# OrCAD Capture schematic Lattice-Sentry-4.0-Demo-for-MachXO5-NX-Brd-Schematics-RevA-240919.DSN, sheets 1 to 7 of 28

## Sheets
1 Title Page: title: Sentry 4.0 Board for XO5D; rev: 1.1; note: 305-PD-24-0xxx
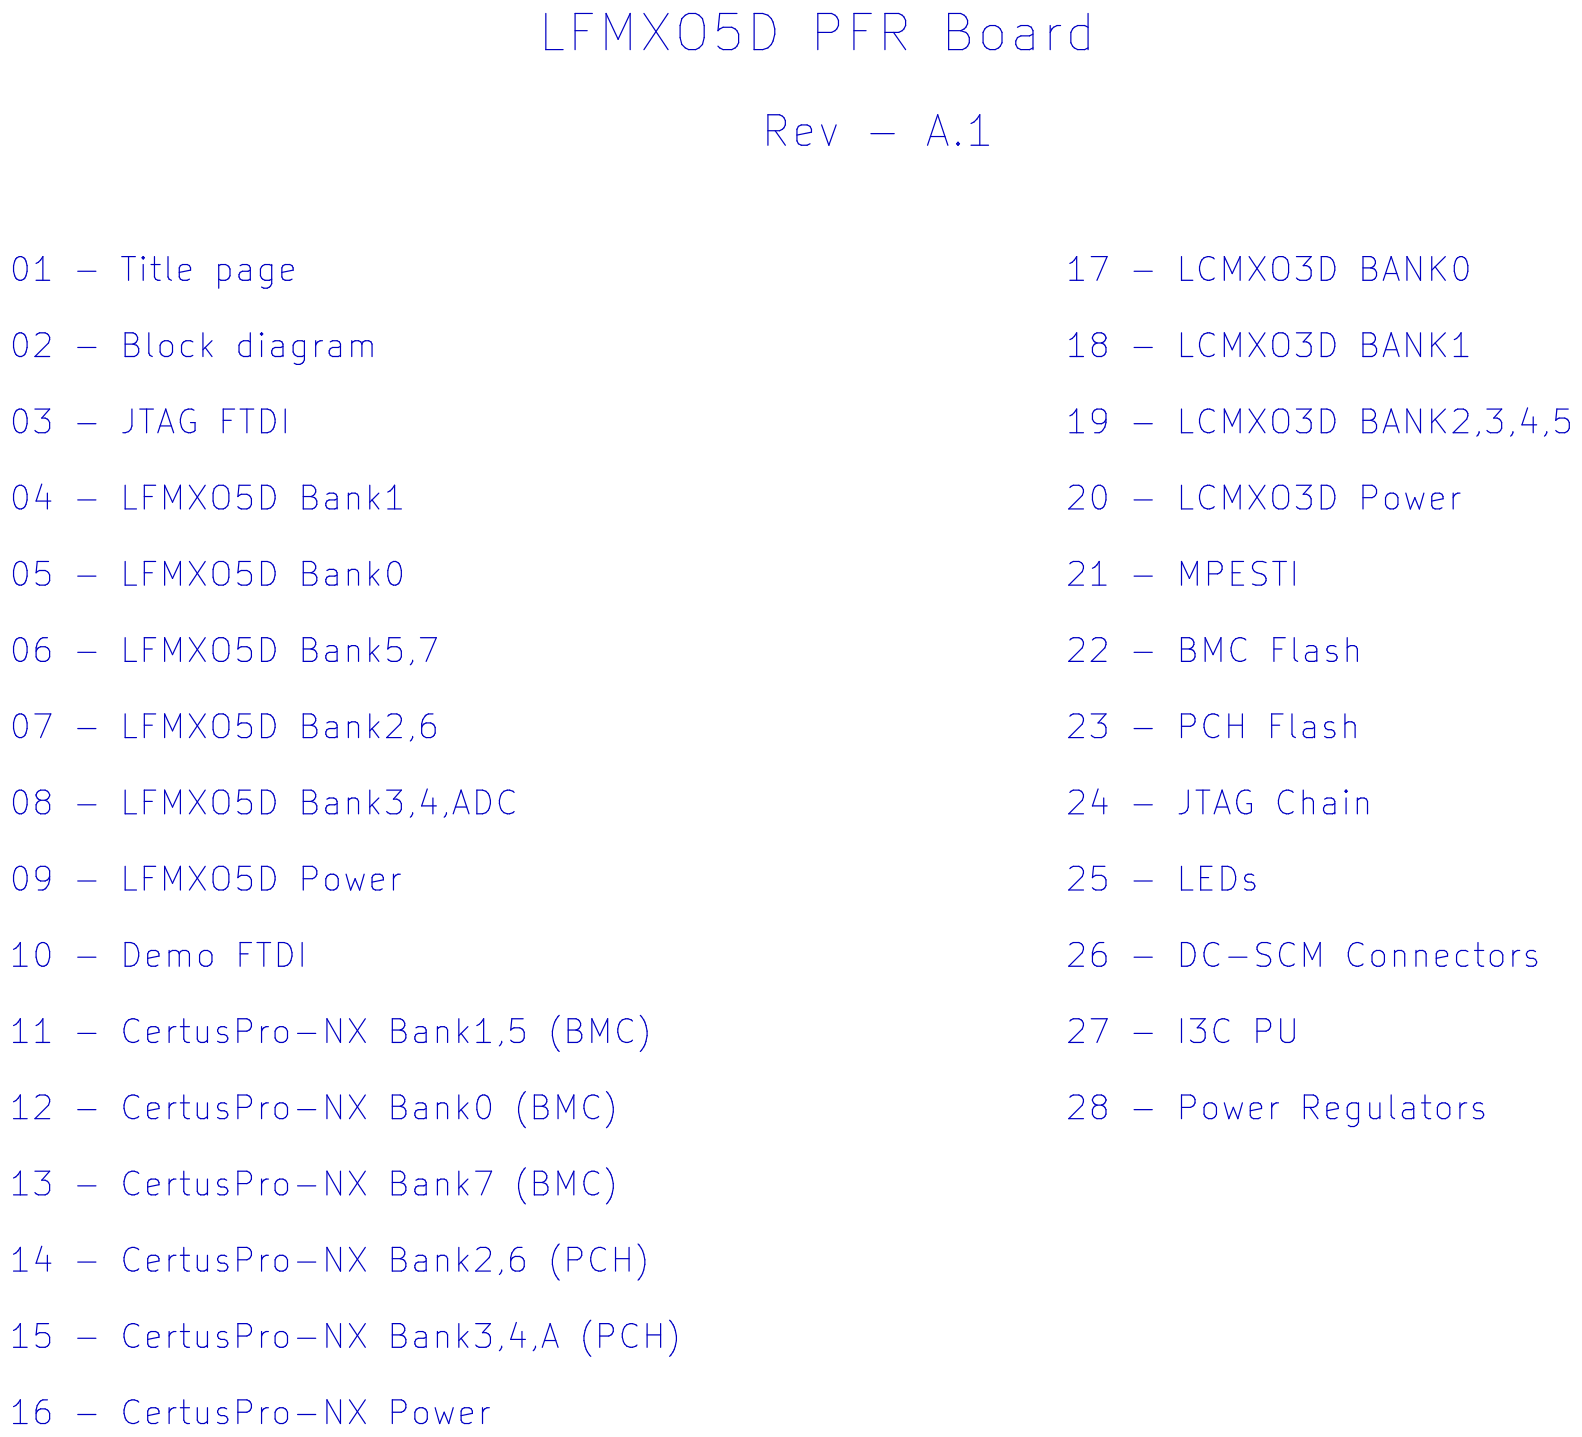
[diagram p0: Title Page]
2 Block Diagram
3 JTAG FTDI: size B
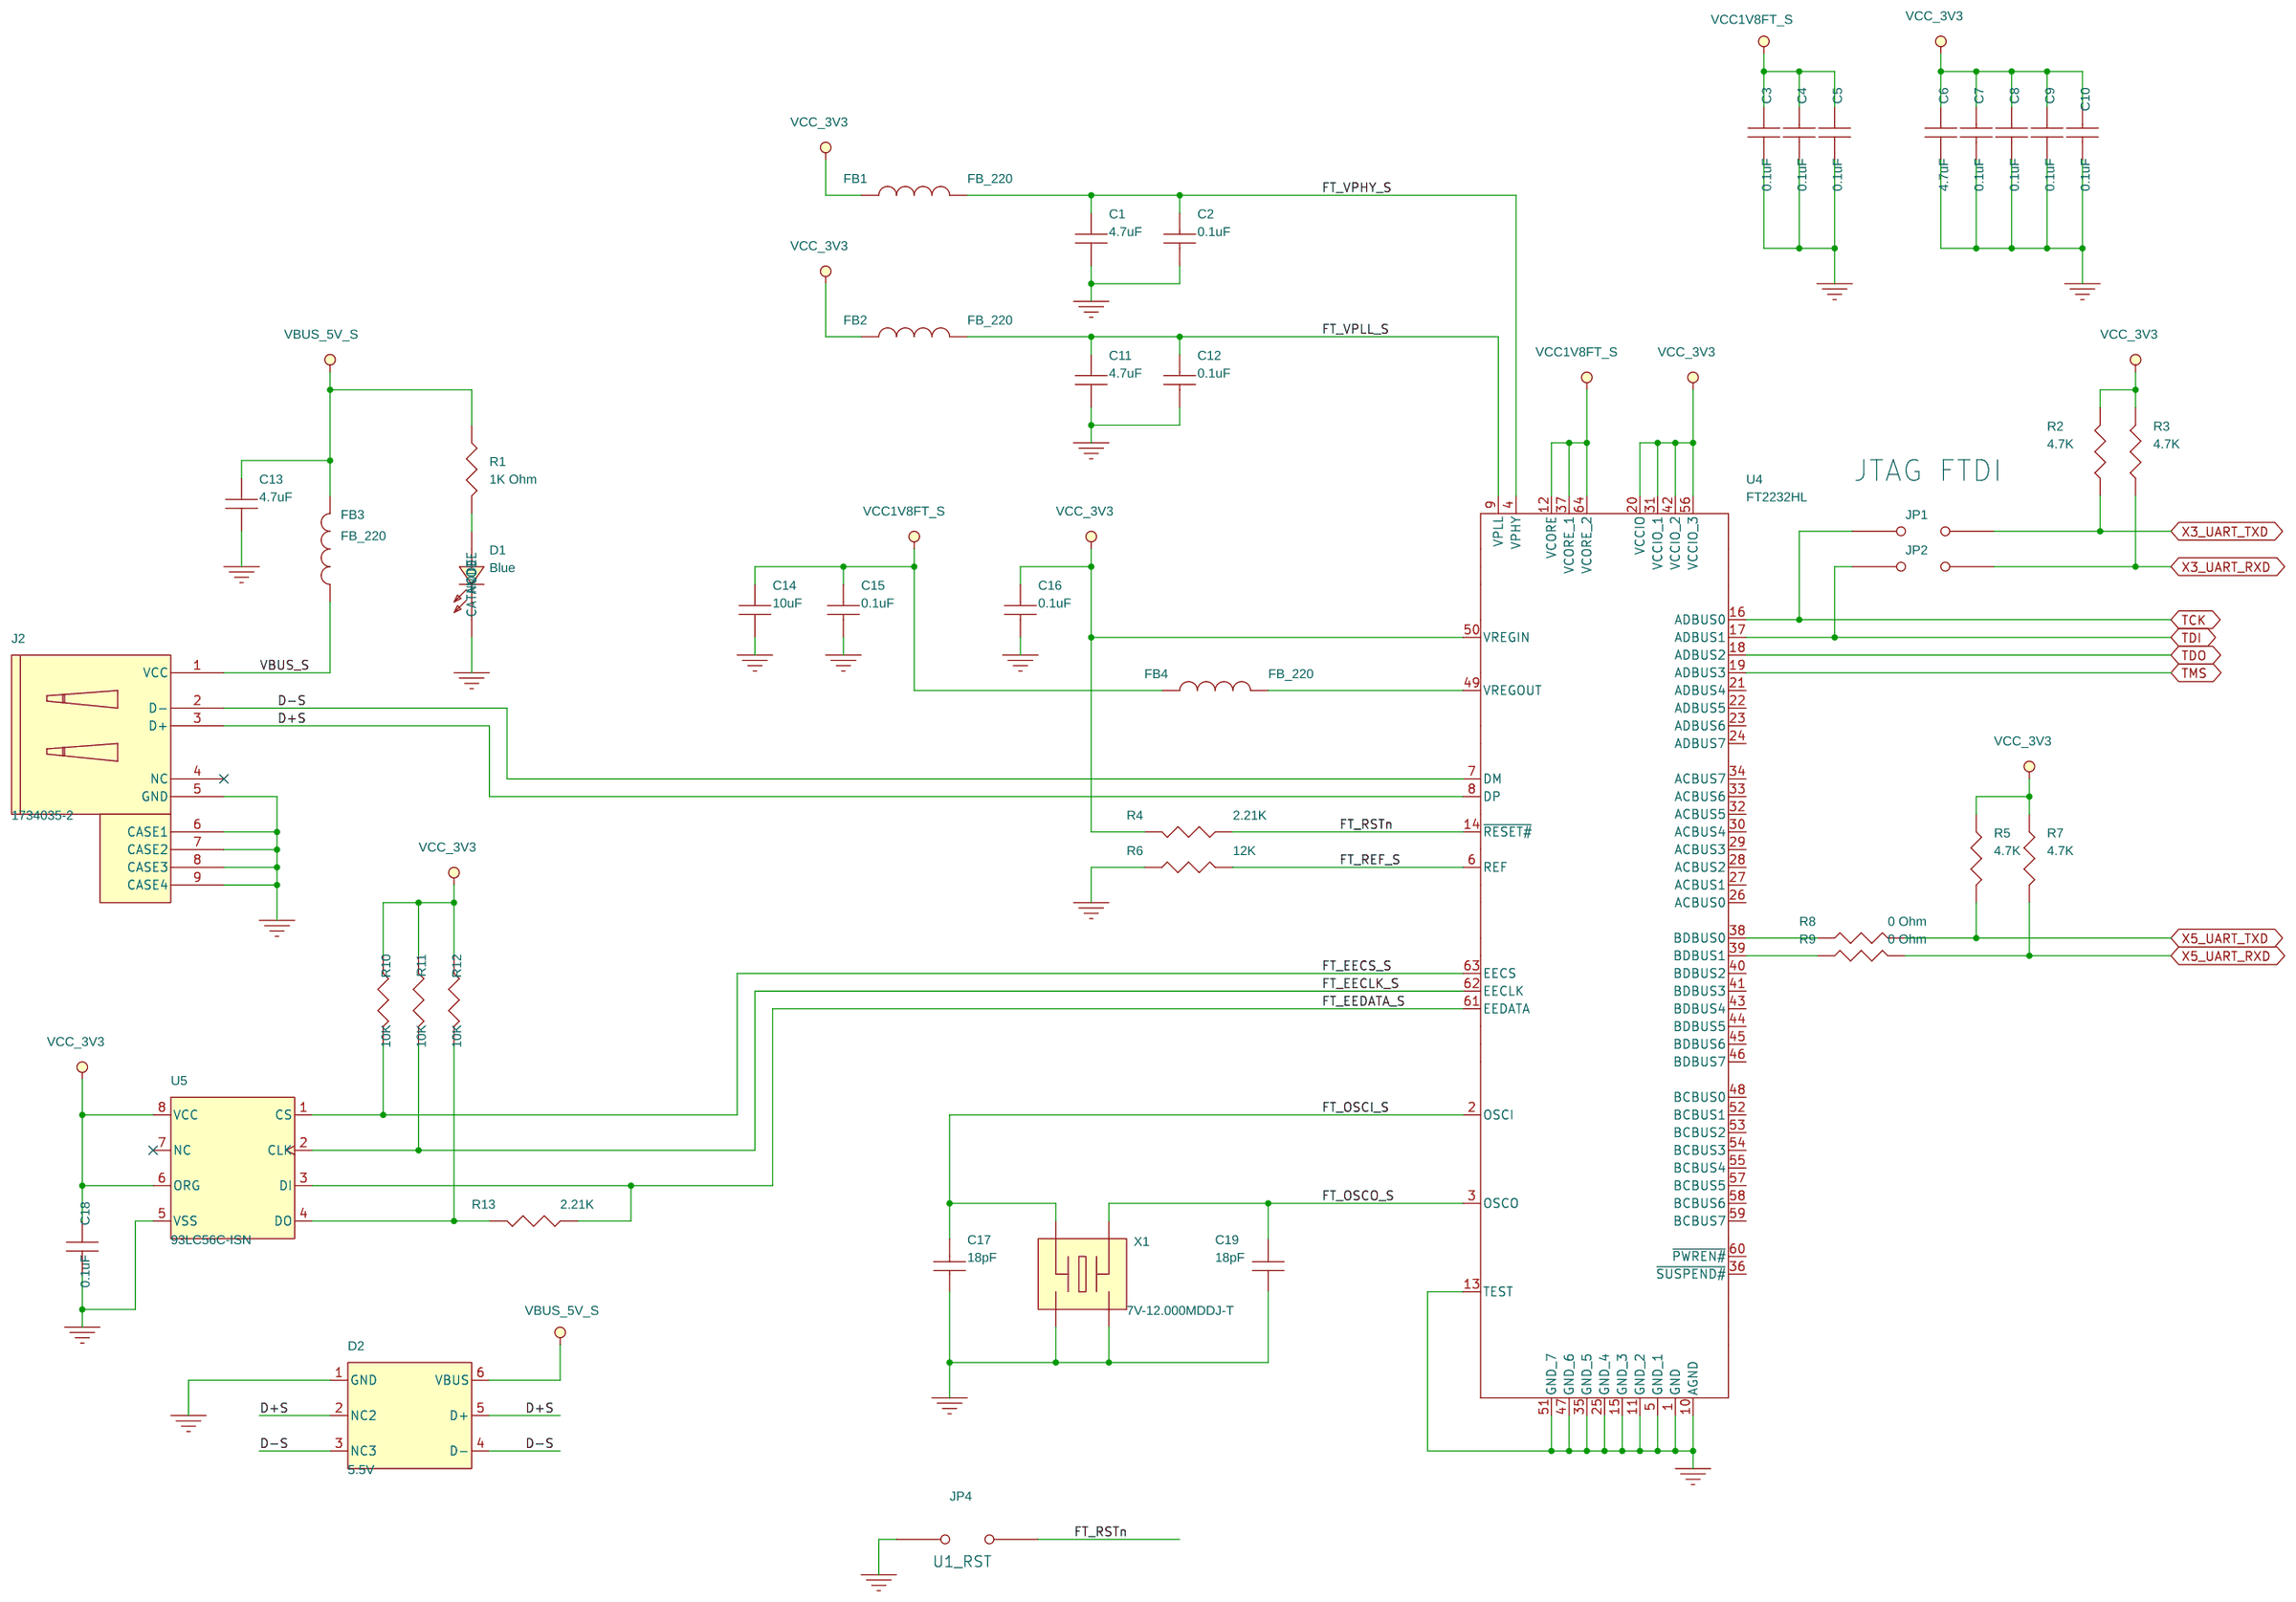
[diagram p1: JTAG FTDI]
4 LFMXO5D Bank1: size B
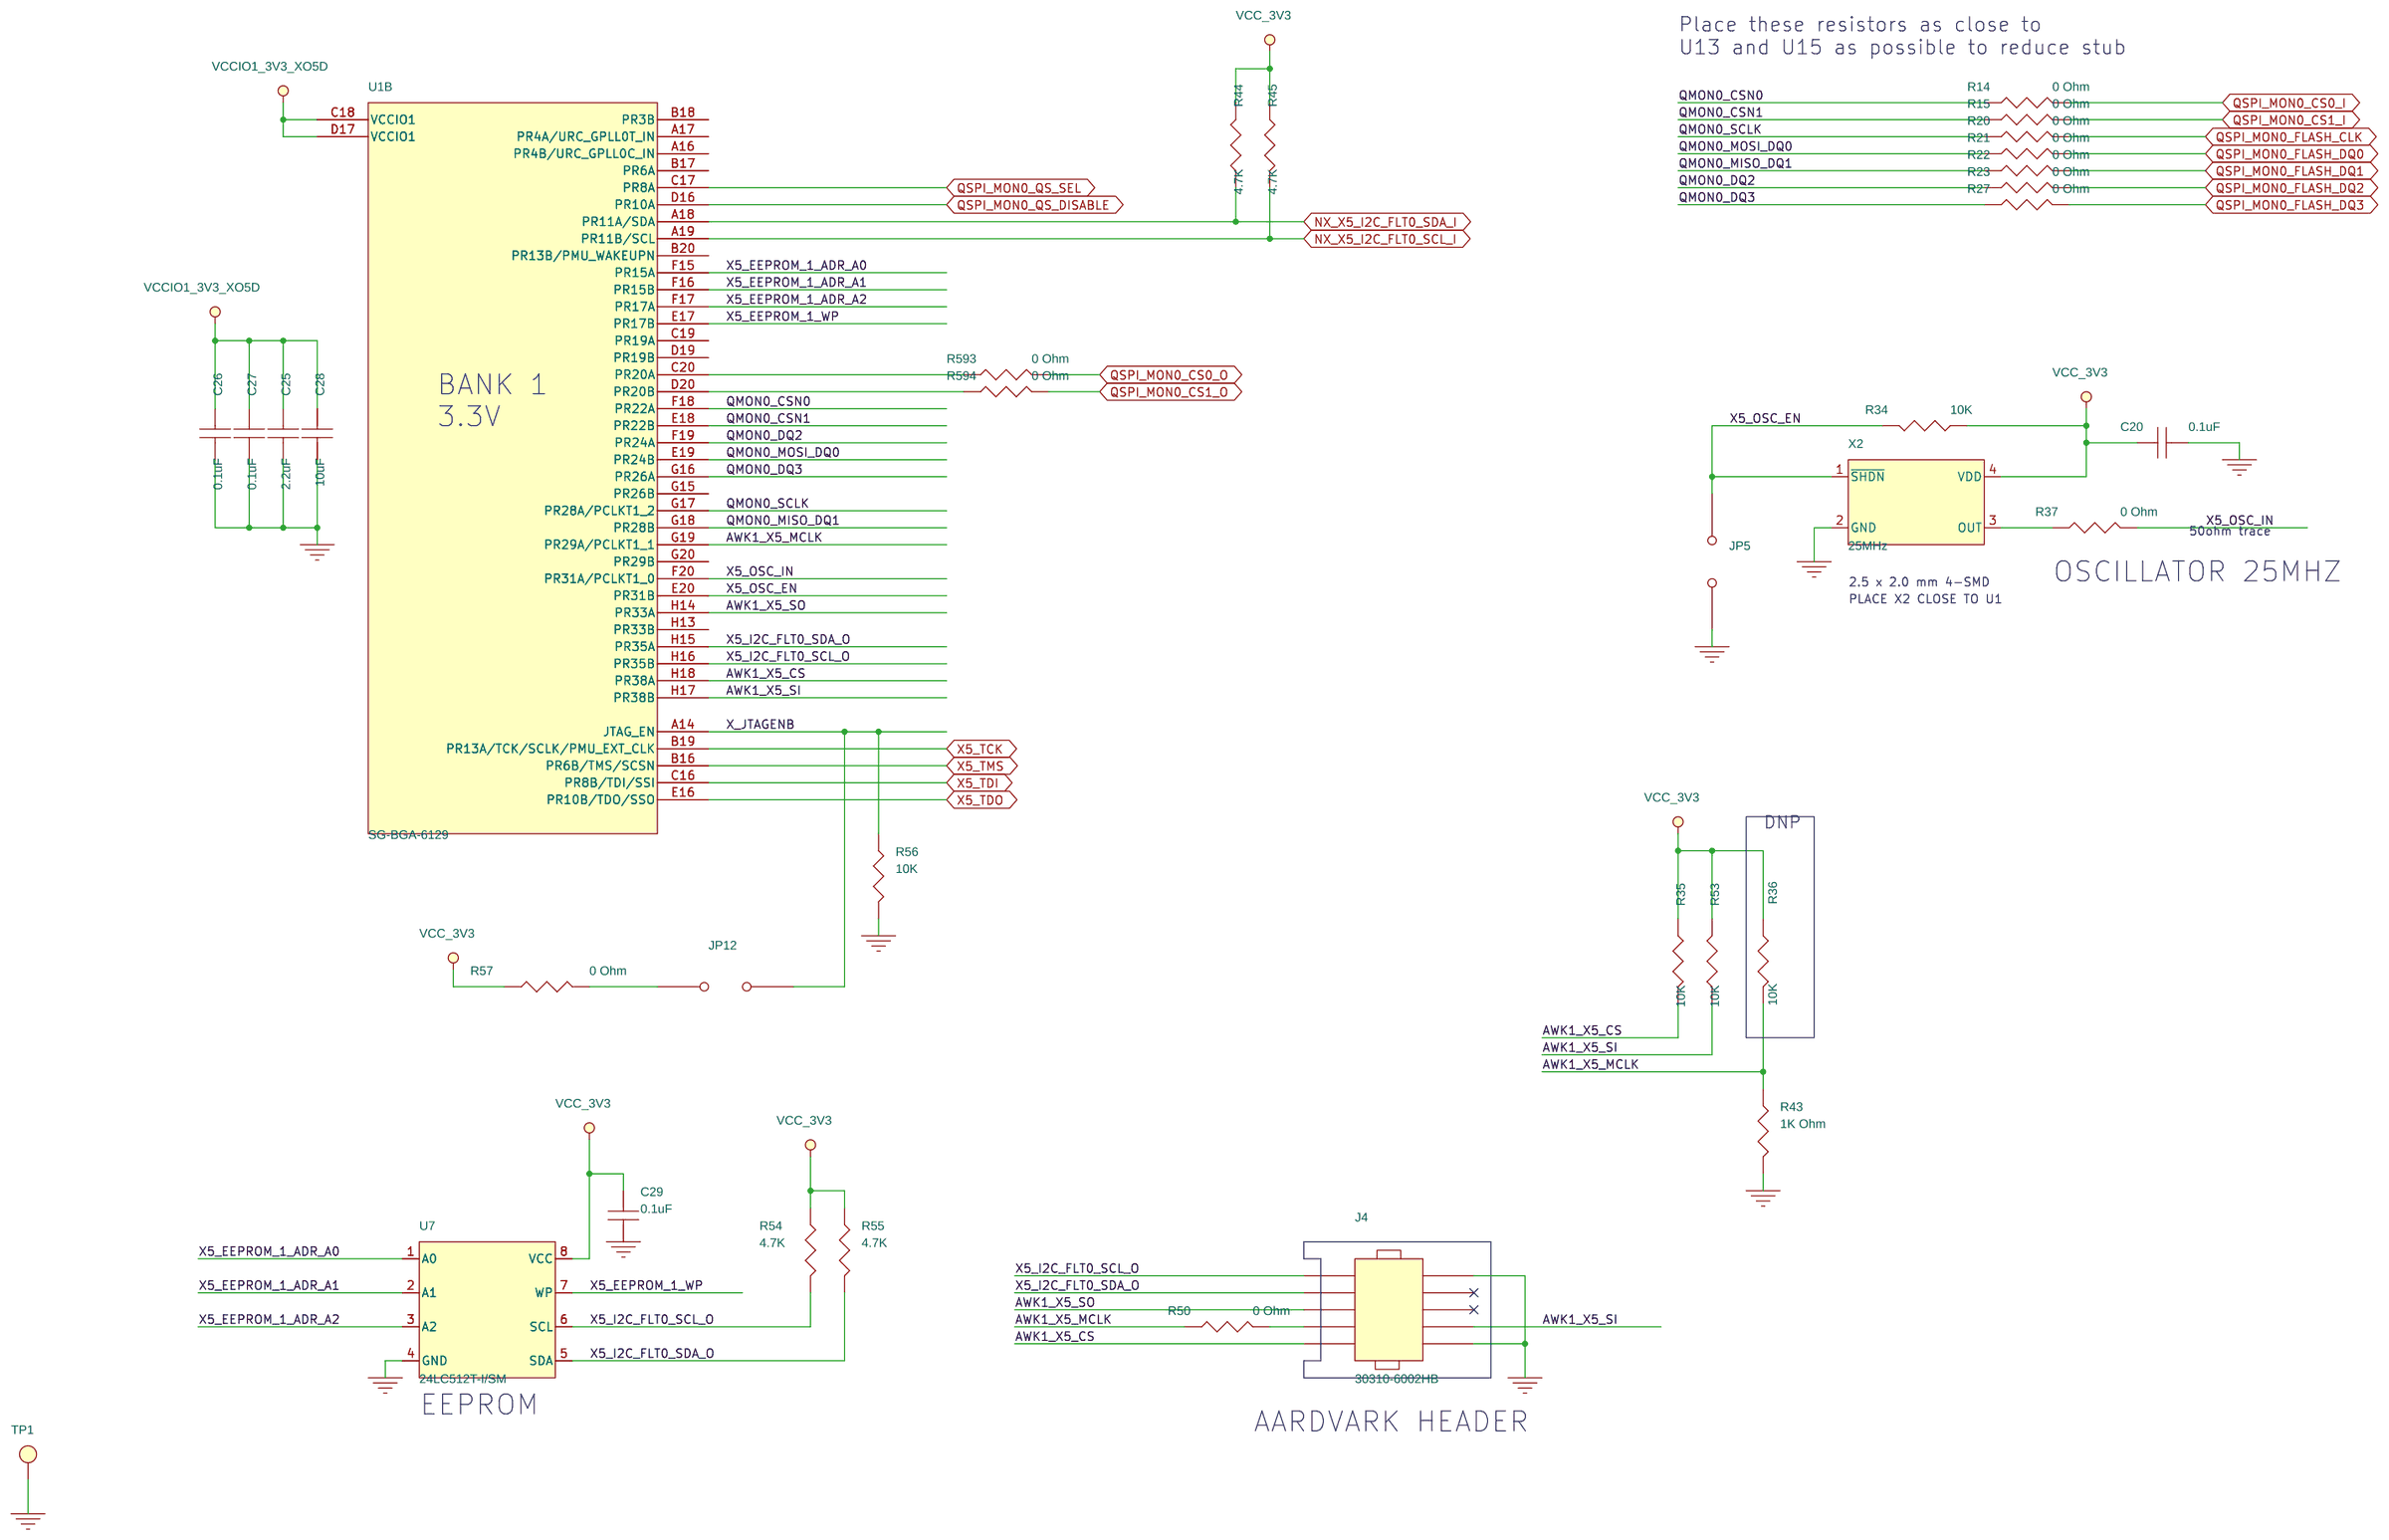
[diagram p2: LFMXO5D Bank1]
5 LFMXO5D Bank0: size B
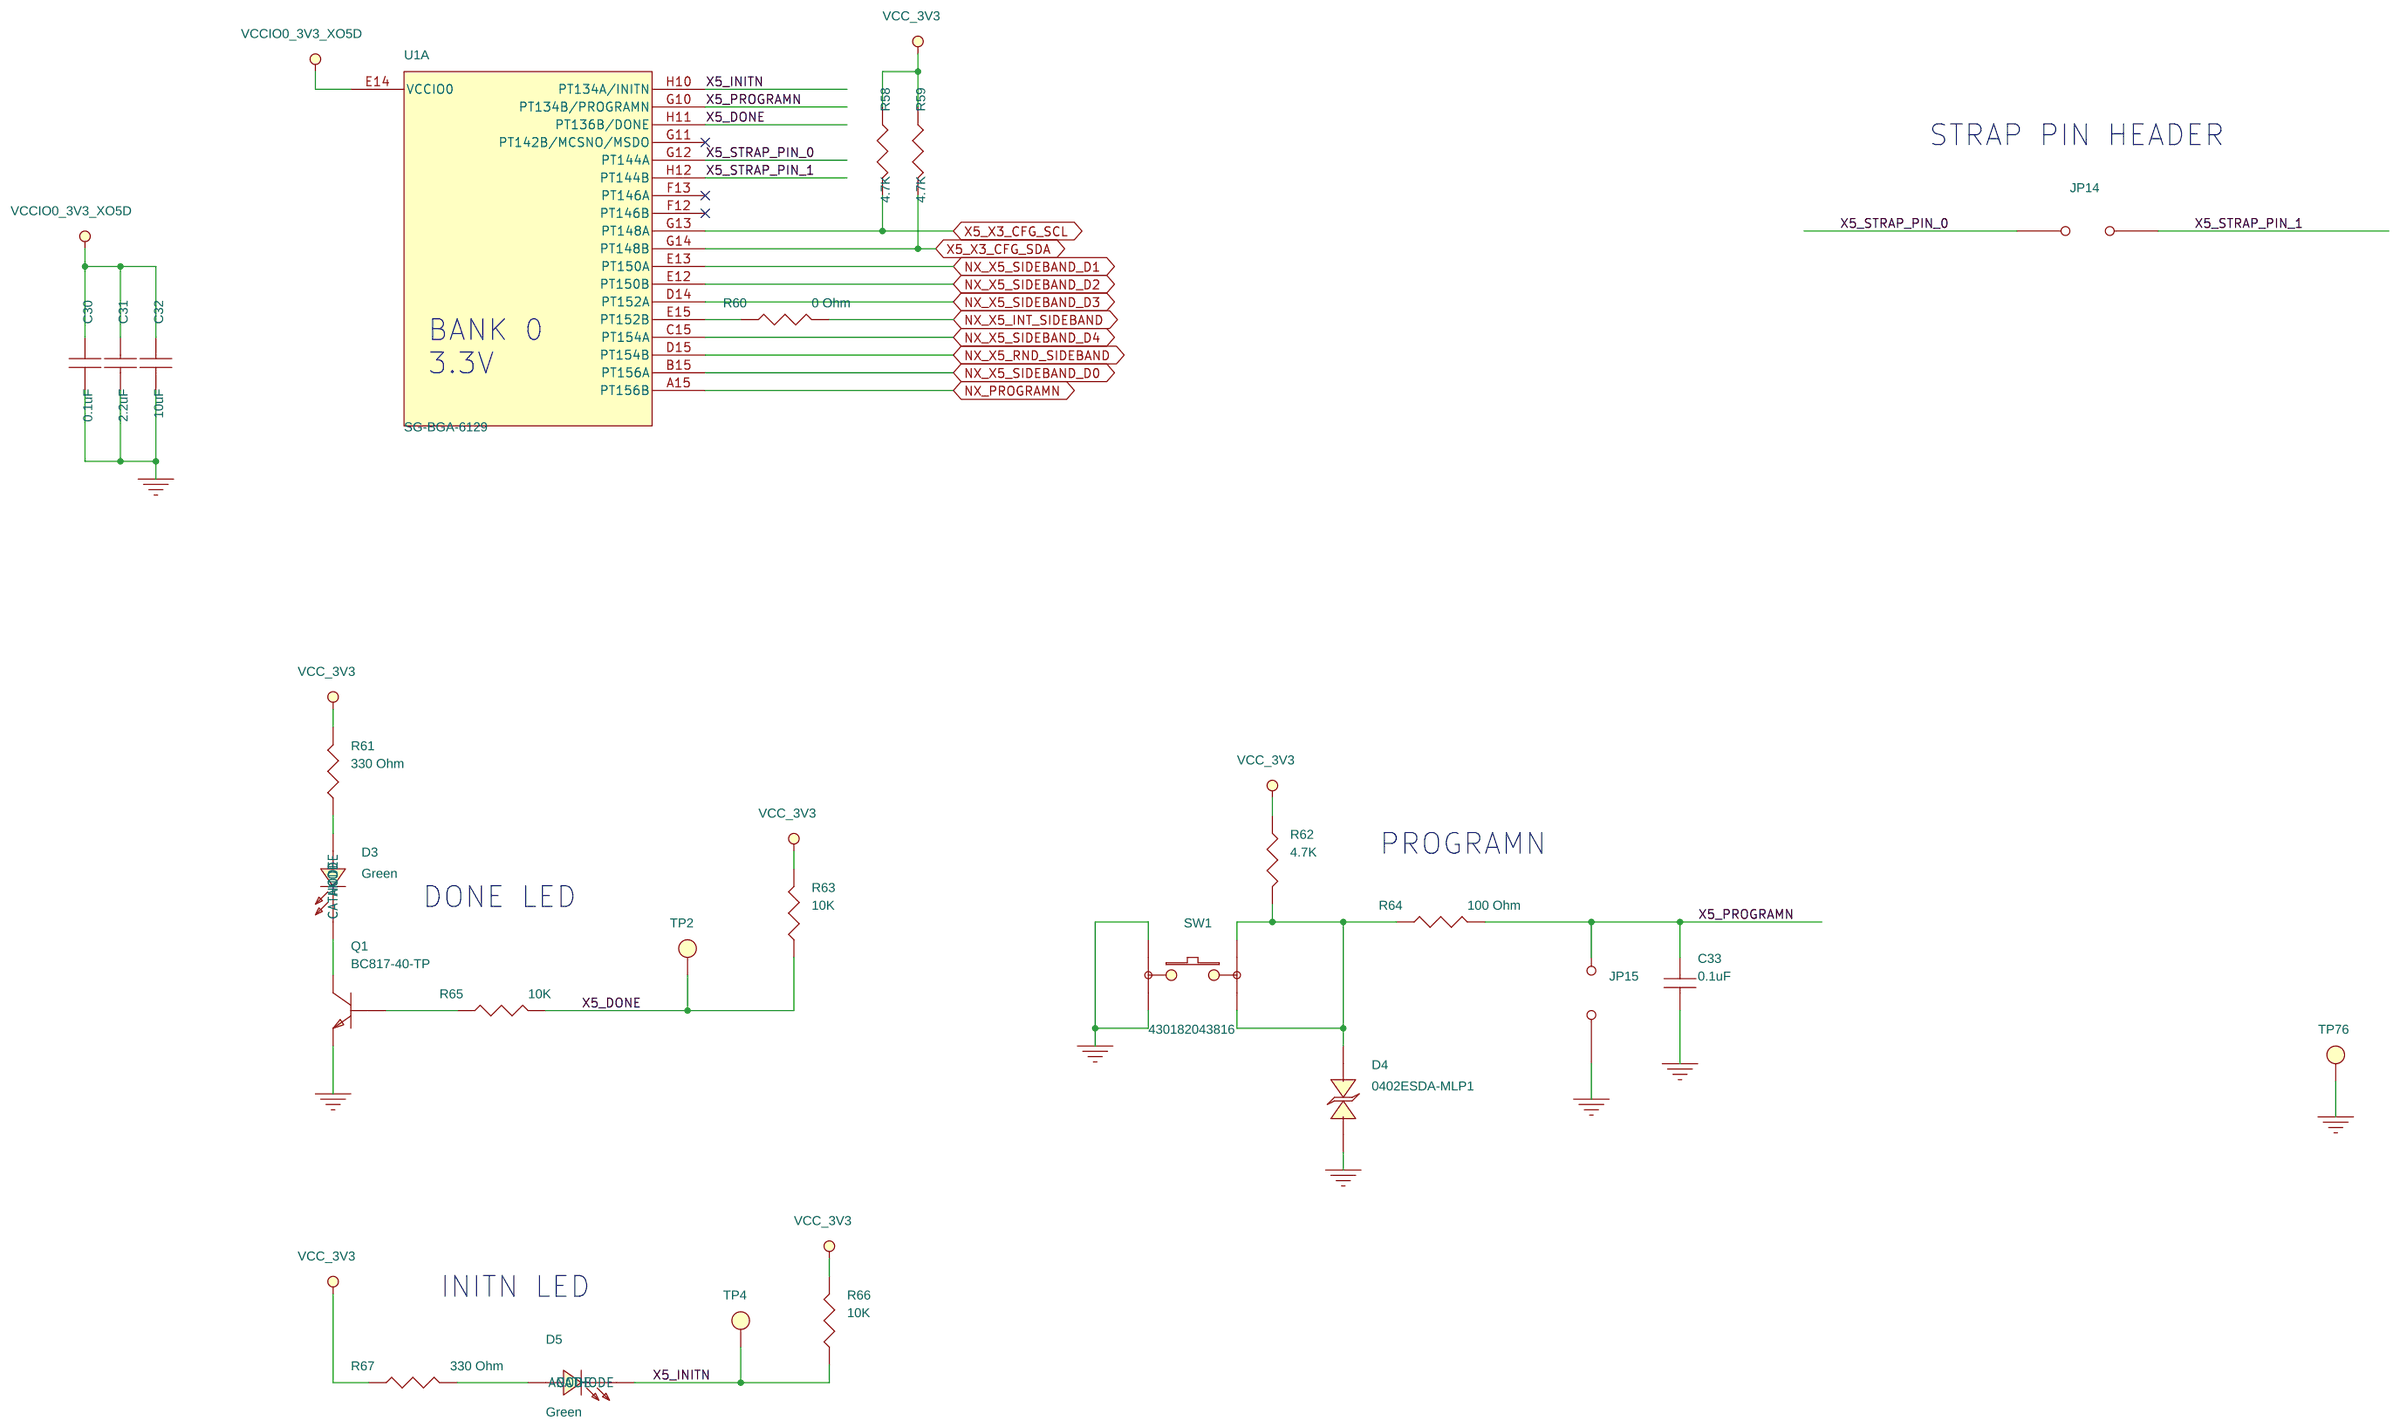
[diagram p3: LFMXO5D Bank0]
6 LFMXO5D Bank5,7: size B
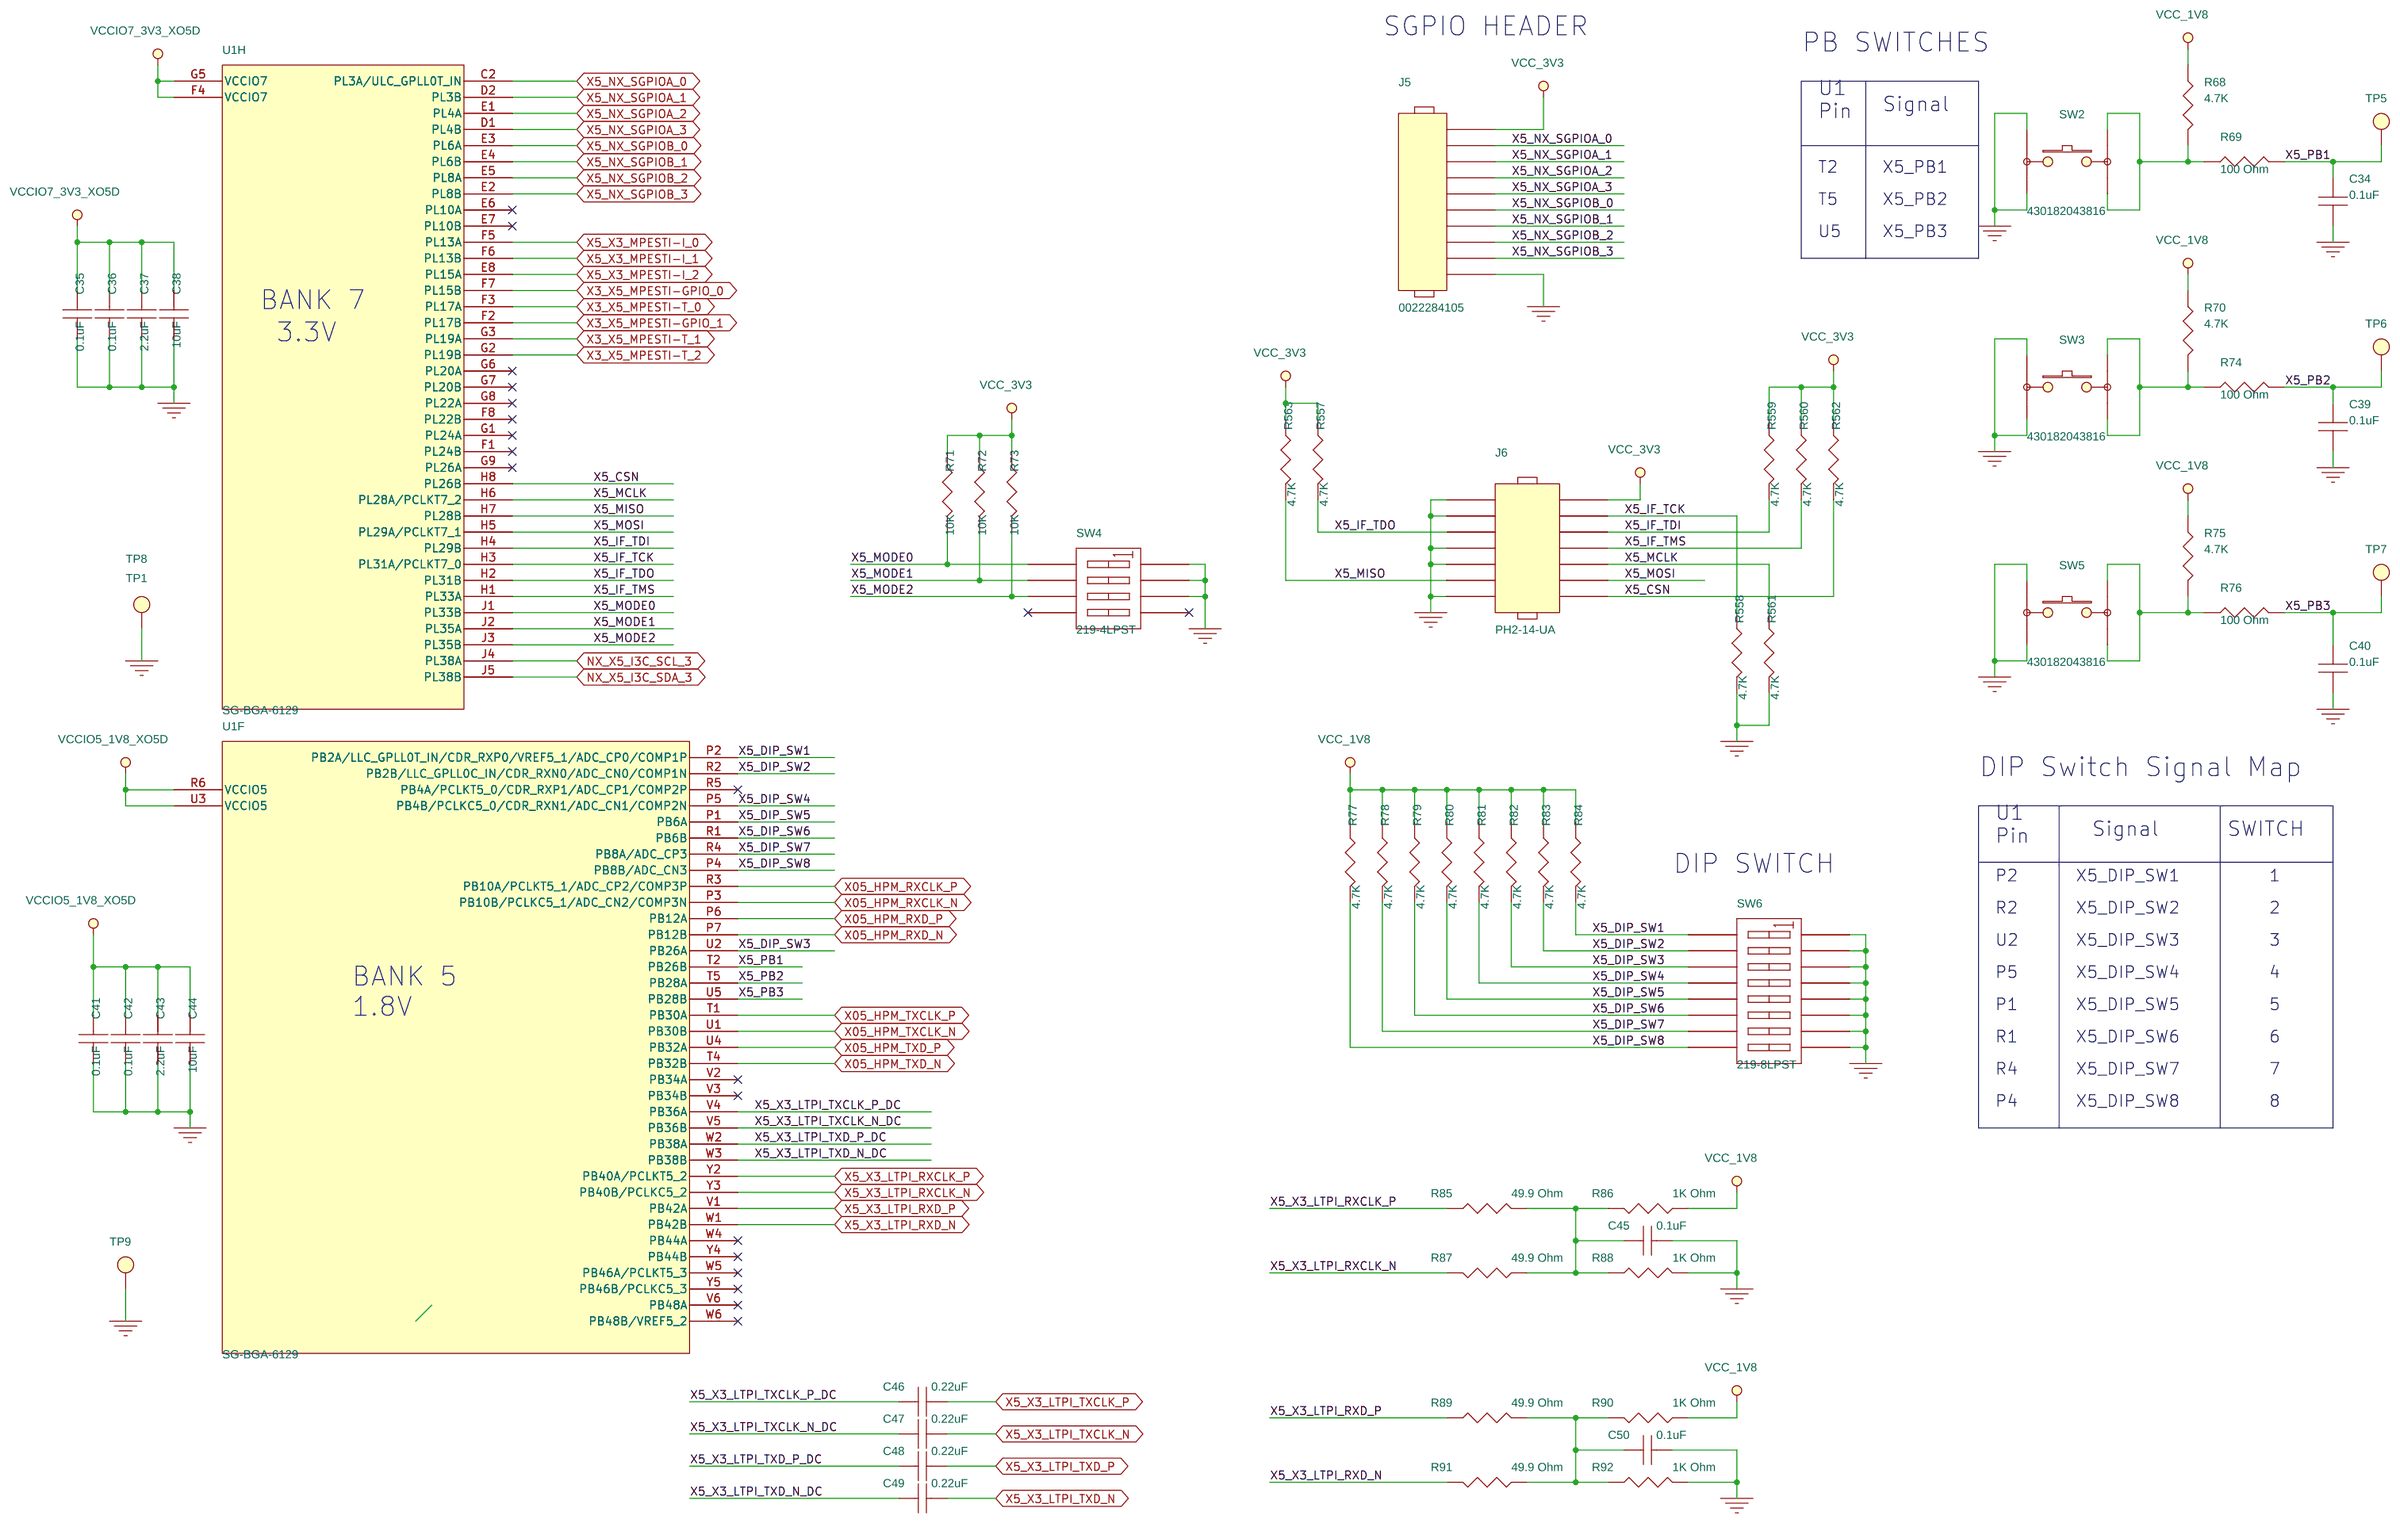
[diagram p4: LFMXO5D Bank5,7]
7 LFMXO5D Bank2,6: size B
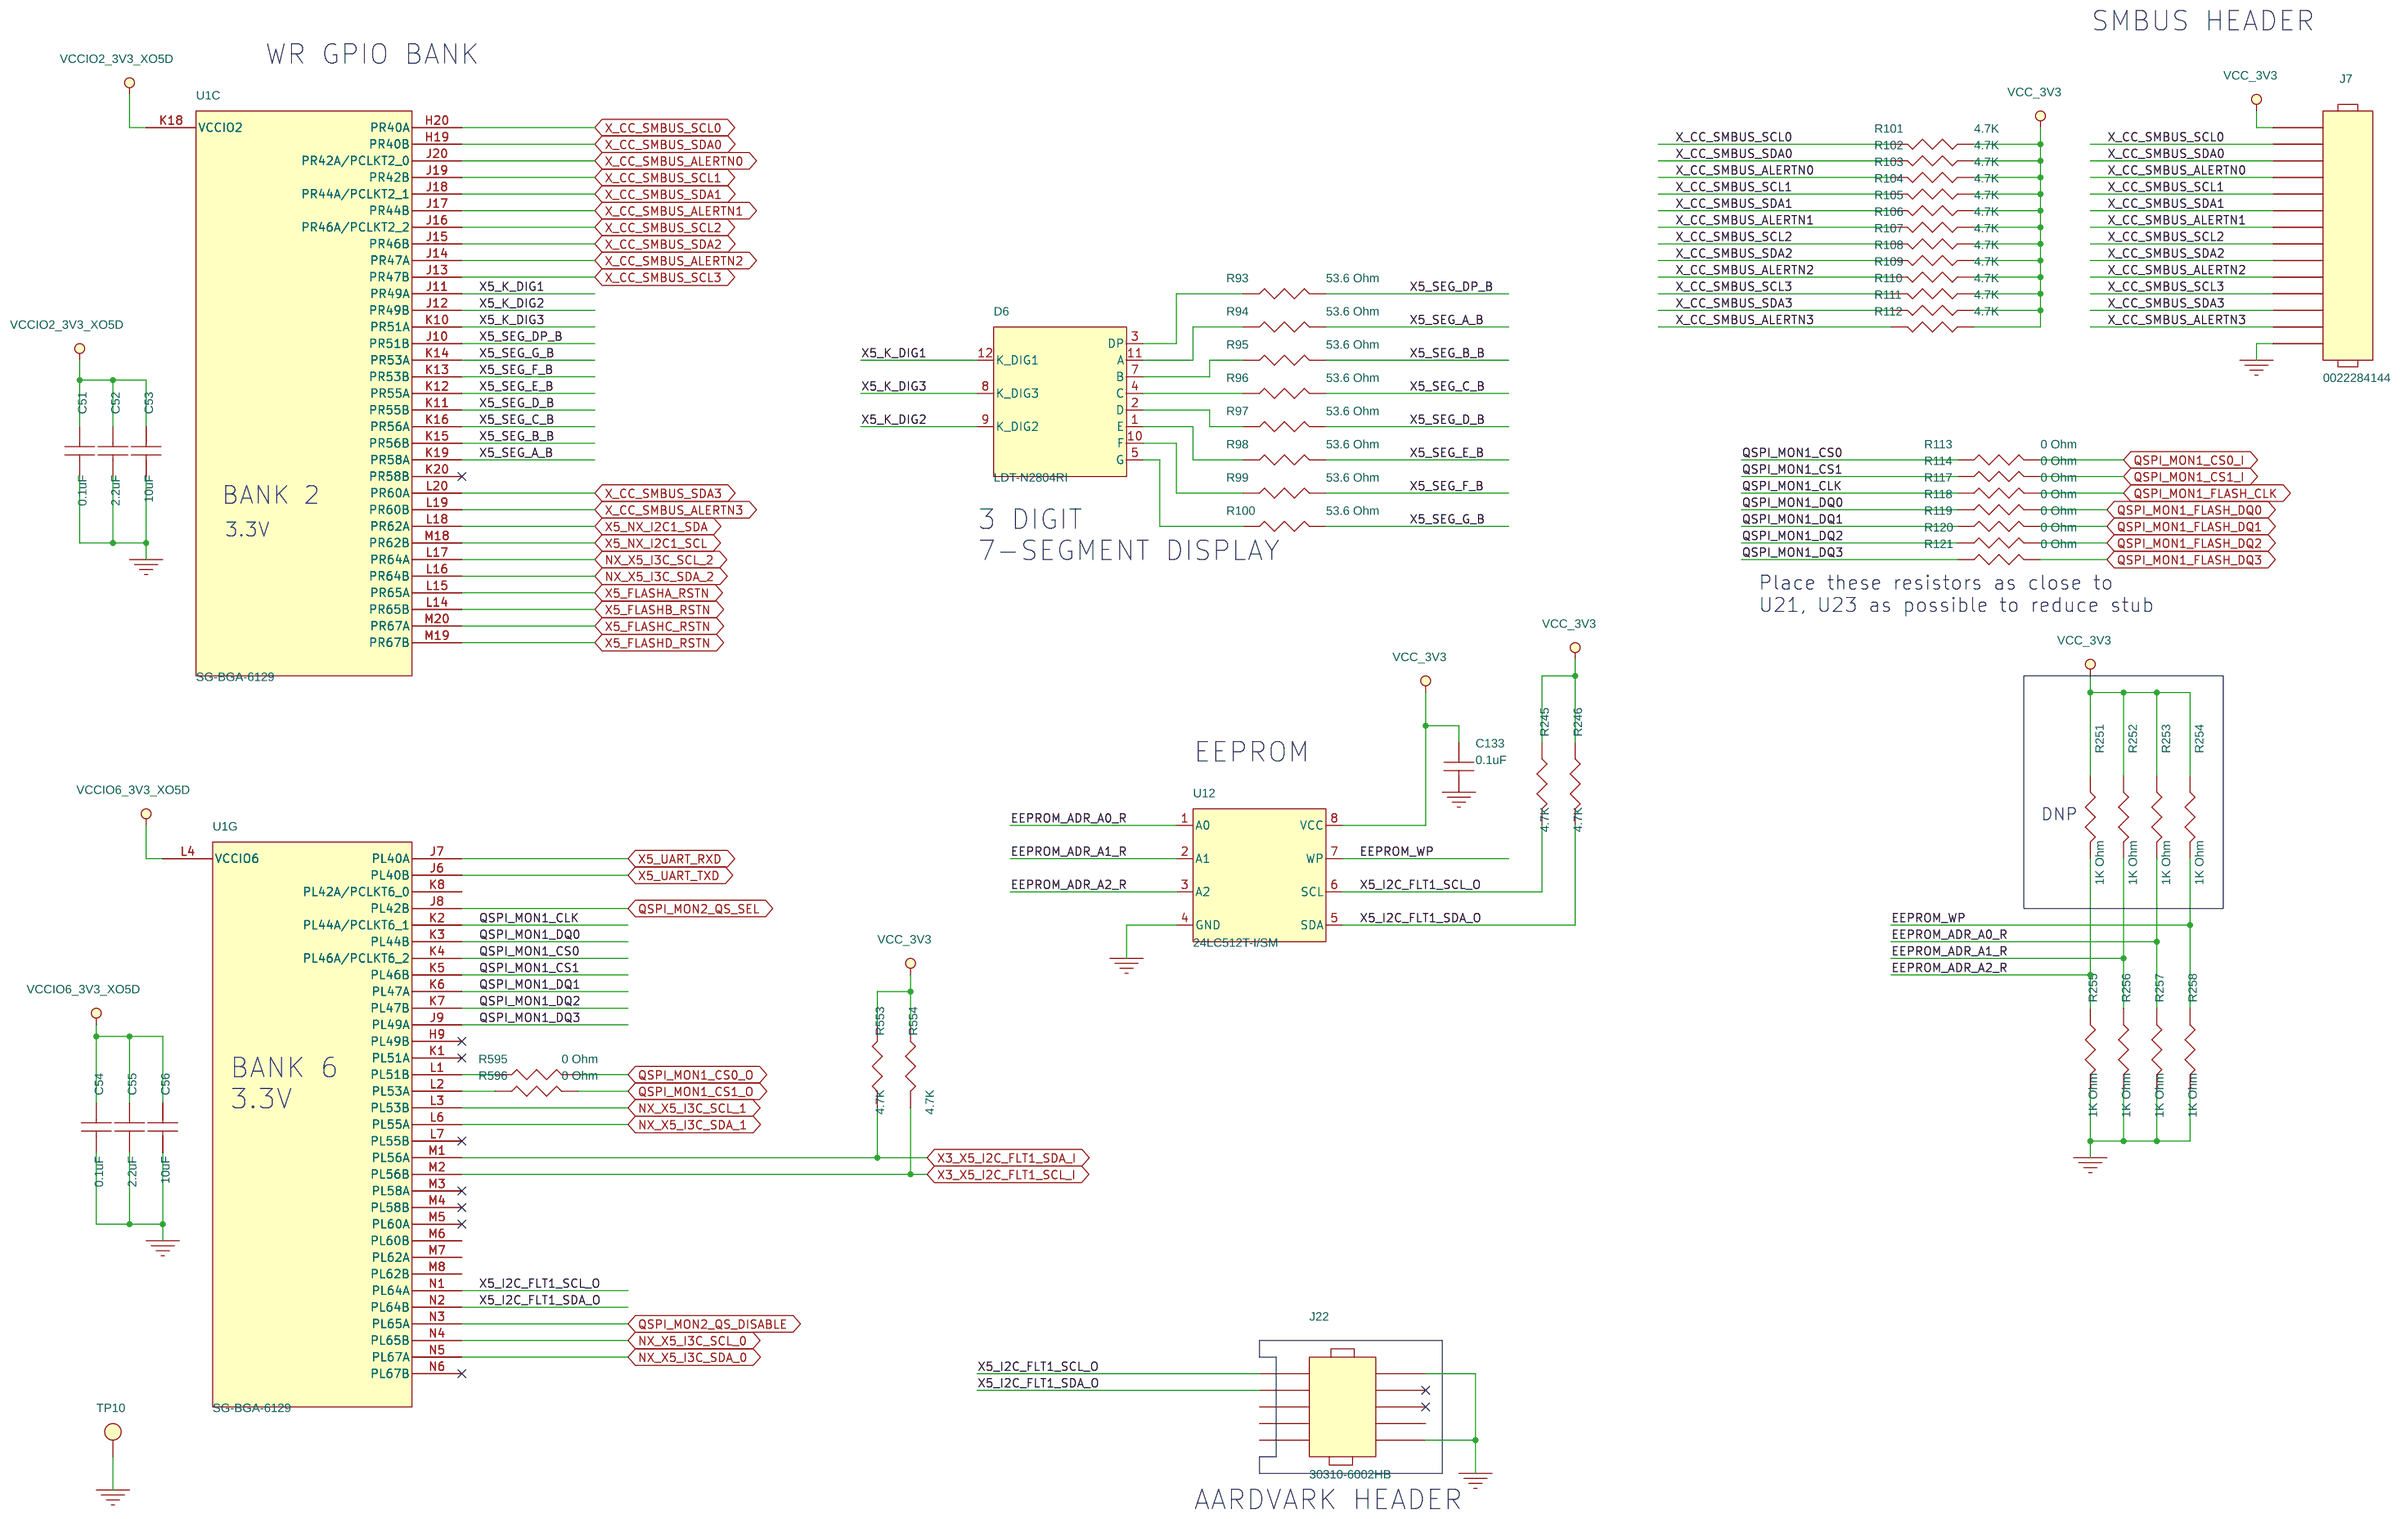
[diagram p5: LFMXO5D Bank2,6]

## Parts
sheet JTAG FTDI
C1  4.7uF  [C0603-L]
C2  0.1uF  [C0402-L]
C3  0.1uF  [C0402-L]
C4  0.1uF  [C0402-L]
C5  0.1uF  [C0402-L]
C6  4.7uF  [C0603-L]
C7  0.1uF  [C0402-L]
C8  0.1uF  [C0402-L]
C9  0.1uF  [C0402-L]
C10  0.1uF  [C0402-L]
C11  4.7uF  [C0603-L]
C12  0.1uF  [C0402-L]
C13  4.7uF  [C0603-L]
C14  10uF  [C0805-L]
C15  0.1uF  [C0402-L]
C16  0.1uF  [C0402-L]
C17  18pF  [C0402-L]
C18  0.1uF  [C0402-L]
C19  18pF  [C0402-L]
D1  Blue  [LED0603]
D2  5.5V  [UDFN6_1P2X1]
FB1  FB_220  [IND_1608_TDK]
FB2  FB_220  [IND_1608_TDK]
FB3  FB_220  [IND_1608_TDK]
FB4  FB_220  [IND_1608_TDK]
J2  1734035-2  [CONN5_USB1734035_TEC]
JP1  Jumper  [CONN2_M20-999_1x2_HRW]
JP2  Jumper  [CONN2_M20-999_1x2_HRW]
JP4  Jumper  [CONN2_M20-999_1x2_HRW]
R1  1K Ohm  [R0402-L]
R2  4.7K  [R0402-L]
R3  4.7K  [R0402-L]
R4  2.21K  [R0402-L]
R5  4.7K  [R0402-L]
R6  12K  [R0402-L]
R7  4.7K  [R0402-L]
R8  0 Ohm  [R0402-L]
R9  0 Ohm  [R0402-L]
R10  10K  [R0402-L]
R11  10K  [R0402-L]
R12  10K  [R0402-L]
R13  2.21K  [R0402-L]
U4  FT2232HL  [64L-LQFP]
U5  93LC56C-ISN  [SOIC8-N]
X1  7V-12.000MDDJ-T  [SMD_0MAHE-T_TXC-L]
sheet LFMXO5D Bank0
C30  0.1uF  [C0402-L]
C31  2.2uF  [C0603-L]
C32  10uF  [C0805-L]
C33  0.1uF  [C0402-L]
D3  Green  [LED0603]
D4  0402ESDA-MLP1  [TVS0402]
D5  Green  [LED0603]
JP14  Jumper  [CONN2_M20-999_1x2_HRW]
JP15  Jumper  [CONN2_M20-999_1x2_HRW]
Q1  BC817-40-TP  [SOT-23-3]
R58  4.7K  [R0402-L]
R59  4.7K  [R0402-L]
R60  0 Ohm  [R0402-L]
R61  330 Ohm  [R0402-L]
R62  4.7K  [R0402-L]
R63  10K  [R0402-L]
R64  100 Ohm  [R0402-L]
R65  10K  [R0402-L]
R66  10K  [R0402-L]
R67  330 Ohm  [R0402-L]
SW1  430182043816  [SOIC_82043816_WRE]
TP2  TP1  [TPd39c60]
TP4  TP1  [TPd39c60]
TP76  TP1  [TPd39c60]
sheet LFMXO5D Bank1
C20  0.1uF  [C0402-L]
C25  2.2uF  [C0603-L]
C26  0.1uF  [C0402-L]
C27  0.1uF  [C0402-L]
C28  10uF  [C0805-L]
C29  0.1uF  [C0402-L]
J4  30310-6002HB  [CONN_30310-6002HB_3MM]
JP5  Jumper  [CONN2_M20-999_1x2_HRW]
JP12  Jumper  [CONN2_M20-999_1x2_HRW]
R14  0 Ohm  [R0402-L]
R15  0 Ohm  [R0402-L]
R20  0 Ohm  [R0402-L]
R21  0 Ohm  [R0402-L]
R22  0 Ohm  [R0402-L]
R23  0 Ohm  [R0402-L]
R27  0 Ohm  [R0402-L]
R34  10K  [R0402-L]
R35  10K  [R0402-L]
R36  10K  [R0402-L]
R37  0 Ohm  [R0402-L]
R43  1K Ohm  [R0402-L]
R44  4.7K  [R0402-L]
R45  4.7K  [R0402-L]
R50  0 Ohm  [R0402-L]
R53  10K  [R0402-L]
R54  4.7K  [R0402-L]
R55  4.7K  [R0402-L]
R56  10K  [R0402-L]
R57  0 Ohm  [R0402-L]
R593  0 Ohm  [R0402-L]
R594  0 Ohm  [R0402-L]
TP1  TP1  [TPd39c60]
U7  24LC512T-I/SM  [SOIC8-W_MC_MCH]
X2  25MHz  [ECS-2520MV_ECS]
sheet LFMXO5D Bank2,6
C51  0.1uF  [C0402-L]
C52  2.2uF  [C0603-L]
C53  10uF  [C0805-L]
C54  0.1uF  [C0402-L]
C55  2.2uF  [C0603-L]
C56  10uF  [C0805-L]
C133  0.1uF  [C0402-L]
D6  LDT-N2804RI  [LDT-N2804RI_LUM]
J7  0022284144  [22-28-4144_MOL]
J22  30310-6002HB  [CONN_30310-6002HB_3MM]
R93  53.6 Ohm  [R0402-L]
R94  53.6 Ohm  [R0402-L]
R95  53.6 Ohm  [R0402-L]
R96  53.6 Ohm  [R0402-L]
R97  53.6 Ohm  [R0402-L]
R98  53.6 Ohm  [R0402-L]
R99  53.6 Ohm  [R0402-L]
R100  53.6 Ohm  [R0402-L]
R101  4.7K  [R0402-L]
R102  4.7K  [R0402-L]
R103  4.7K  [R0402-L]
R104  4.7K  [R0402-L]
R105  4.7K  [R0402-L]
R106  4.7K  [R0402-L]
R107  4.7K  [R0402-L]
R108  4.7K  [R0402-L]
R109  4.7K  [R0402-L]
R110  4.7K  [R0402-L]
R111  4.7K  [R0402-L]
R112  4.7K  [R0402-L]
R113  0 Ohm  [R0402-L]
R114  0 Ohm  [R0402-L]
R117  0 Ohm  [R0402-L]
R118  0 Ohm  [R0402-L]
R119  0 Ohm  [R0402-L]
R120  0 Ohm  [R0402-L]
R121  0 Ohm  [R0402-L]
R245  4.7K  [R0402-L]
R246  4.7K  [R0402-L]
R251  1K Ohm  [R0402-L]
R252  1K Ohm  [R0402-L]
R253  1K Ohm  [R0402-L]
R254  1K Ohm  [R0402-L]
R255  1K Ohm  [R0402-L]
R256  1K Ohm  [R0402-L]
R257  1K Ohm  [R0402-L]
R258  1K Ohm  [R0402-L]
R553  4.7K  [R0402-L]
R554  4.7K  [R0402-L]
R595  0 Ohm  [R0402-L]
R596  0 Ohm  [R0402-L]
TP10  TP1  [TPd39c60]
U12  24LC512T-I/SM  [SOIC8-W_MC_MCH]
sheet LFMXO5D Bank5,7
C34  0.1uF  [C0402-L]
C35  0.1uF  [C0402-L]
C36  0.1uF  [C0402-L]
C37  2.2uF  [C0603-L]
C38  10uF  [C0805-L]
C39  0.1uF  [C0402-L]
C40  0.1uF  [C0402-L]
C41  0.1uF  [C0402-L]
C42  0.1uF  [C0402-L]
C43  2.2uF  [C0603-L]
C44  10uF  [C0805-L]
C45  0.1uF  [C0402-L]
C46  0.22uF  [C0402-L]
C47  0.22uF  [C0402-L]
C48  0.22uF  [C0402-L]
C49  0.22uF  [C0402-L]
C50  0.1uF  [C0402-L]
J5  0022284105  [22-28-4105_MOL]
J6  PH2-14-UA  [CONN_PH2-14-UA_AT]
R68  4.7K  [R0402-L]
R69  100 Ohm  [R0402-L]
R70  4.7K  [R0402-L]
R71  10K  [R0402-L]
R72  10K  [R0402-L]
R73  10K  [R0402-L]
R74  100 Ohm  [R0402-L]
R75  4.7K  [R0402-L]
R76  100 Ohm  [R0402-L]
R77  4.7K  [R0402-L]
R78  4.7K  [R0402-L]
R79  4.7K  [R0402-L]
R80  4.7K  [R0402-L]
R81  4.7K  [R0402-L]
R82  4.7K  [R0402-L]
R83  4.7K  [R0402-L]
R84  4.7K  [R0402-L]
R85  49.9 Ohm  [R0402-L]
R86  1K Ohm  [R0402-L]
R87  49.9 Ohm  [R0402-L]
R88  1K Ohm  [R0402-L]
R89  49.9 Ohm  [R0402-L]
R90  1K Ohm  [R0402-L]
R91  49.9 Ohm  [R0402-L]
R92  1K Ohm  [R0402-L]
R557  4.7K  [R0402-L]
R558  4.7K  [R0402-L]
R559  4.7K  [R0402-L]
R560  4.7K  [R0402-L]
R561  4.7K  [R0402-L]
R562  4.7K  [R0402-L]
R563  4.7K  [R0402-L]
SW2  430182043816  [SOIC_82043816_WRE]
SW3  430182043816  [SOIC_82043816_WRE]
SW4  219-4LPST  [219-4LP_CTS]
SW5  430182043816  [SOIC_82043816_WRE]
SW6  219-8LPST  [219-8LPST_CTS]
TP5  TP1  [TPd39c60]
TP6  TP1  [TPd39c60]
TP7  TP1  [TPd39c60]
TP8  TP1  [TPd39c60]
TP9  TP1  [TPd39c60]
U1  SG-BGA-6129  [bga400_socket]  (sections A,B,C,D,E,F,G,H,I,J,K,L)

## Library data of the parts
C1 C6 C11 C13 = CAP_NP: 4.7 µF ±10% 25V Ceramic Capacitor X5R 0603 (1608 Metric); Manufacturer: TDK; Manufacturer Part Number: C1608X5R1E475K080AC; Part Number: C1608X5R1E475K080AC; Part type: Ceramic; Tolerance: 10%; Voltage: 25V; Datasheet: https://product.tdk.com/system/files/dam/doc/product/capacitor/ceramic/mlcc/catalog/mlcc_commercial_general_en.pdf
C2-C5 C7-C10 C12 C15 C16 C18 C20 C26 C27 C29 C30 C33-C36 C39-C42 C45 C50 C51 C54 C133 = CAP_NP: 0.1 µF ±10% 50V Ceramic Capacitor X7R 0402 (1005 Metric); Manufacturer: Murata; Manufacturer Part Number: GRM155R71H104KE14J; Part Number: GRM155R71H104KE14J; Part type: Ceramic; Tolerance: 10%; Voltage: 50V; Datasheet: https://search.murata.co.jp/Ceramy/image/img/A01X/G101/ENG/GRM155R71H104KE14-01.pdf
C14 C28 C32 C38 C44 C53 C56 = CAP_NP: 10 µF ±10% 25V Ceramic Capacitor X5R 0805 (2012 Metric); Manufacturer: Murata; Manufacturer Part Number: GRM21BR61E106KA73K; Part Number: GRM21BR61E106KA73K; Part type: Ceramic; Tolerance: 10%; Voltage: 25V; Datasheet: https://search.murata.co.jp/Ceramy/image/img/A01X/G101/ENG/GRM21BR61E106KA73-01.pdf
C17 C19 = CAP_NP: 18 pF ±5% 50V Ceramic Capacitor C0G, NP0 0402 (1005 Metric); Manufacturer: Yageo; Manufacturer Part Number: CC0402JRNPO9BN180; Part Number: CC0402JRNPO9BN180; Part type: Ceramic; Tolerance: 5%; Voltage: 50V; Datasheet: https://www.yageo.com/upload/media/product/productsearch/datasheet/mlcc/UPY-GP_NP0_16V-to-50V_18.pdf
D1 = LED_0: Blue 470nm LED Indication - Discrete 2.9V 0603 (1608 Metric); Manufacturer: Lumex; Manufacturer Part Number: SMLD12BN1WT86; Part Number: SMLD12BN1WT86; Part type: LED; Voltage: 2.9V; Datasheet: https://www.rohm.com/datasheet?p=SMLD12BN1W&dist=Digi-key&media=referral&source=digi-key.com&campaign=Digi-key
D2 = ESDR0502: Clamp Ipp Tvs Diode Surface Mount 6-UDFN (1.2x1); Current: 100W; MANUFACTURER: ONSEMI; MFR PART NO.: ESDR0502NMUTBG; Manufacturer Part Number: ESDR0502NMUTAG; PACKAGE: 6-UFDFN; PART DESCRIPTION: TVS DIODE 5.5VWM 6UDFN; Part Number: ESDR0502NMUTAG; Part type: TVS; Datasheet: https://www.onsemi.com/pdf/datasheet/esdr0502n-d.pdf
FB1-FB4 = INDUCTOR: 220 Ohms @ 100 MHz 1 Power Line Ferrite Bead 0603 (1608 Metric) 2.2A 50mOhm; Current: 2.2A; DCR: 50 mOhm; Manufacturer: Murata Electronics; Manufacturer Part Number: BLM18KG221SN1D; Part Number: BLM18KG221SN1D; Datasheet: https://www.murata.com/products/productdata/8796738650142/ENFA0003.pdf
J2 = USB_MINI_B: USB - mini B USB 2.0 Receptacle Connector 5 Position Surface Mount, Right Angle; MANUFACTURER: TE Connectivity; MFR PART NO.: 690-005-299-043; PACKAGE: SMD; PART DESCRIPTION: CONN RCPT USB2.0 MINI B SMD R/A; Part Type: Connector; Populate: <Populate>; Datasheet: https://www.te.com/commerce/DocumentDelivery/DDEController?Action=srchrtrv&DocNm=1734035&DocType=Customer+Drawing&DocLang=English
JP1 JP2 JP4 JP5 JP14 JP15 = JUMPER: Connector Header Through Hole 2 position 0.100" (2.54mm); Manufacturer: Sullins; Manufacturer Part Number: PREC002SAAN-RC; Part Number: PREC002SAAN-RC; Datasheet: https://media.digikey.com/PDF/Data%20Sheets/Sullins%20PDFs/z%20RzCzzzSzzN-RC,%20ST,11635-B.pdf
R1 R43 R86 R88 R90 R92 R255-R258 = R: 1 kOhms ±1% 0.063W, 1/16W Chip Resistor 0402 (1005 Metric) Thick Film; Manufacturer: Yageo; Manufacturer Part Number: RC0402FR-71K2P / RC0402FR-0733R2P; Part Number: RC0402FR-071KP / RC0402FR-0733R2P / RC0402FR-0733R2P; Part type: Thick Film; Power: 1/16W; Tolerance: 1%; Datasheet: https://www.yageo.com/upload/media/product/products/datasheet/rchip/PYu-RC_51_RoHS_P_4.pdf
R2 R3 = R: 4.7 kOhms ±1% 0.063W, 1/16W Chip Resistor 0402 (1005 Metric) Thick Film; MFR PART NO.: CRCW06032K20FKEA; Manufacturer: Yageo; Manufacturer Part Number: RC0402FR-074K7P; PACKAGE: 0603; PART DESCRIPTION: RES SMD 2.2K OHM 1% 1/10W 0603; Part Number: RC0402FR-074K7P; Part type: Thick Film; Populate: <Populate>; Power: 1/16W; Tolerance: 1%; Datasheet: https://www.yageo.com/upload/media/product/products/datasheet/rchip/PYu-RC_51_RoHS_P_4.pdf
R4 R13 = R: 2.21 kOhms ±1% 0.063W, 1/16W Chip Resistor 0402 (1005 Metric) Thick Film; Manufacturer: Yageo; Manufacturer Part Number: RC0402FR-072K21L; Part Number: RC0402FR-072K21L; Part type: Thick Film; Power: 1/16W; Tolerance: 1%; Datasheet: https://www.yageo.com/upload/media/product/productsearch/datasheet/rchip/PYu-RC_Group_51_RoHS_L_12.pdf
R5 R7 R44 R45 R54 R55 R58 R59 R62 R68 R70 R75 R77-R84 R101-R112 R245 R246 R553 R554 R557-R563 = R: 4.7 kOhms ±1% 0.063W, 1/16W Chip Resistor 0402 (1005 Metric) Thick Film; Manufacturer: Yageo; Manufacturer Part Number: RC0402FR-074K7P; Part Number: RC0402FR-074K7P; Part type: Thick Film; Power: 1/16W; Tolerance: 1%; Datasheet: https://www.yageo.com/upload/media/product/products/datasheet/rchip/PYu-RC_51_RoHS_P_4.pdf
R6 = R: 12 kOhms ±1% 0.063W, 1/16W Chip Resistor 0402 (1005 Metric) Moisture Resistant Thick Film; Manufacturer: Yageo; Manufacturer Part Number: RC0402FR-0712KL; Part Number: RC0402FR-0712KL; Part type: Thick Film; Power: 1/16W; Tolerance: 1%; Datasheet: https://www.yageo.com/upload/media/product/productsearch/datasheet/rchip/PYu-RC_Group_51_RoHS_L_12.pdf
R8 R9 R14 R15 R20-R23 R27 R37 R50 R57 R60 R113 R114 R117-R121 R593-R596 = R: 0 Ohms Jumper Chip Resistor 0402 (1005 Metric) Moisture Resistant Thick Film; Manufacturer: Yageo; Manufacturer Part Number: RC0402FR-070RL; Part Number: RC0402FR-070RL; Part type: Thick Film; Datasheet: https://www.yageo.com/upload/media/product/productsearch/datasheet/rchip/PYu-RC_Group_51_RoHS_L_12.pdf
R10-R12 R35 R53 R56 R63 R65 R66 R71-R73 = R: 10 kOhms ±1% 0.063W, 1/16W Chip Resistor 0402 (1005 Metric) Thick Film; Manufacturer: Yageo; Manufacturer Part Number: RC0402FR-0710KP; Part Number: RC0402FR-0710KP; Part type: Thick Film; Power: 1/16W; Tolerance: 1%; Datasheet: https://www.yageo.com/upload/media/product/products/datasheet/rchip/PYu-RC_51_RoHS_P_4.pdf
U4 = FT2232HQ-REEL_3: IC USB HS DUAL UART/FIFO 64-LQFP; Manufacturer: FTDI; Manufacturer Part Number: FT2232HL-REEL; Part Number: FT2232HL-REEL; Part Type: USB Bridge; Datasheet: https://www.ftdichip.com/Support/Documents/DataSheets/ICs/DS_FT2232H.pdf
U5 = 93LC56C-I_SN: EEPROM Memory IC 2Kbit Microwire 3 MHz 8-SOIC; Manufacturer: Microchip; Part Type: EEPROM; Datasheet: https://ww1.microchip.com/downloads/en/DeviceDoc/21794G.pdf
X1 = CRYSTAL1-4_SM: 12 MHz ±20ppm Crystal 18pF 150 Ohms 4-SMD, No Lead; Manufacturer: TXC; Part Type: Crystal; Datasheet: http://www.txccrystal.com/images/pdf/7v.pdf
C25 C31 C37 C43 C52 C55 = CAP_NP: 2.2 µF ±10% 25V Ceramic Capacitor X5R 0603 (1608 Metric); Manufacturer: Murata; Manufacturer Part Number: GRM188R61E225KA12J; Part Number: GRM188R61E225KA12J; Part type: Ceramic; Tolerance: 10%; Voltage: 25V; Datasheet: https://search.murata.co.jp/Ceramy/image/img/A01X/G101/ENG/GRM188R61E225KA12-01.pdf
D3 D5 = LED_0: Green 572nm LED indication - Discrete  2.2V 0603; Manufacturer: Rohm Semiconductor; Manufacturer Part Number: SML-D12M8WT86; Part Number: SML-D12M8WT86; Part type: LED; Voltage: 2.2V; Datasheet: https://fscdn.rohm.com/en/products/databook/datasheet/opto/led/chip_mono/sml-d12x8_d13x8-e.pdf
D4 = DIODE_TS_BI-DIR_0: SUPPRESSOR ESD 30VDC 0402 HFREE; Manufacturer: Eaton; Part type: ESD; Voltage: 30V; Datasheet: https://www.eaton.com/content/dam/eaton/products/electronic-components/resources/data-sheet/eaton-0402esda-mlp-esd-suppressor-data-sheet.pdf
Q1 = NPN_BEC_0: Bipolar (BJT) Transistor NPN 45 V 800 mA 100MHz 310 mW Surface Mount SOT-23; Manufacturer: Micro Commercial; Part Type: BJT_NPN; Datasheet: https://www.mccsemi.com/pdf/Products/BC817-16~BC817-40(SOT-23).pdf
R61 R67 = R: 330 Ohms ±1% 0.063W, 1/16W Chip Resistor 0402 (1005 Metric) Moisture Resistant Thick Film; Manufacturer: Yageo; Manufacturer Part Number: RC0402FR-07330RL; Part Number: RC0402FR-07330RL; Part type: Thick Film; Power: 1/16W; Tolerance: 1%; Datasheet: https://www.yageo.com/upload/media/product/productsearch/datasheet/rchip/PYu-RC_Group_51_RoHS_L_12.pdf
R64 R69 R74 R76 = R: 100 Ohms ±1% 0.063W, 1/16W Chip Resistor 0402 (1005 Metric) Thick Film; Manufacturer: Yageo; Manufacturer Part Number: RC0402FR-07100KP; Part Number: RC0402FR-07100KP; Part type: Thick Film; Power: 1/16W; Tolerance: 1%; Datasheet: https://www.yageo.com/upload/media/product/productsearch/datasheet/rchip/PYu-RC_Group_51_RoHS_L_12.pdf
SW1-SW3 SW5 = SW_PB-SPST-2: Tactile Switch SPST-NO Top Actuated Surface Mount; Manufacturer: Wurth; Datasheet: https://www.we-online.com/katalog/datasheet/4301x2xxx8x6.pdf
TP1 TP2 TP4-TP10 TP76 = TP1: Test Point 0.39"; Manufacturer: NA; Part Type: Test Point; Datasheet: NA
J4 J22 = HEADER_5x2: Connector Header Through Hole 10 position 0.100" (2.54mm); Manufacturer: 3M; Part Type: Connector; Datasheet: https://multimedia.3m.com/mws/media/22504O/3mtm-100-in-loprof-hdr-100x-100strt-ra-4-wall-ts0818.pdf
JP12 = JUMPER: Connector Header Through Hole 2 position 0.100" (2.54mm); MANUFACTURER: Sullins; MFR PART NO.: 61300211121; Manufacturer Part Number: PREC002SAAN-RC; PACKAGE: TH; PART DESCRIPTION: CONN HEADER VERT 2POS 2.54MM; Part Number: PREC002SAAN-RC; Datasheet: https://media.digikey.com/PDF/Data%20Sheets/Sullins%20PDFs/z%20RzCzzzSzzN-RC,%20ST,11635-B.pdf
R34 = R: 10 kOhms ±1% 0.063W, 1/16W Chip Resistor 0402 (1005 Metric) Thick Film; MFR PART NO.: RC1608F103CS; Manufacturer: Yageo; Manufacturer Part Number: RC0402FR-0710KP; PACKAGE: 0603; PART DESCRIPTION: RES SMD 10K OHM 1% 1/10W 0603; Part Number: RC0402FR-0710KP; Part type: Thick Film; Power: 1/16W; Tolerance: 1%; Datasheet: https://www.yageo.com/upload/media/product/products/datasheet/rchip/PYu-RC_51_RoHS_P_4.pdf
R36 = R: 10 kOhms ±1% 0.063W, 1/16W Chip Resistor 0402 (1005 Metric) Thick Film; Assy: DNL; Manufacturer: Yageo; Manufacturer Part Number: RC0402FR-0710KP; Part Number: RC0402FR-0710KP; Part type: Thick Film; Power: 1/16W; Tolerance: 1%; Datasheet: https://www.yageo.com/upload/media/product/products/datasheet/rchip/PYu-RC_51_RoHS_P_4.pdf
U7 U12 = 24XX512: EEPROM Memory IC 512Kbit I2C 400 kHz 900 ns 8-SOIJ; Manufacturer: Microchip; Part Type: EEPROM; Datasheet: https://ww1.microchip.com/downloads/en/DeviceDoc/24AA512-24LC512-24FC512-512K-Bit-I2C-Serial-EEPROM-20001754Q.pdf
X2 = OSC4PIN_SM: 25 MHz XO (Standard) HCMOS Oscillator 1.6V ~ 3.6V Enable/Disable 4-SMD, No Lead; Manufacturer: ECS; Manufacturer Part Number: ECS-2520MV-250-CM-TR; Part Number: ECS-2520MV-250-CM-TR; Part Type: Oscillator; Datasheet: https://ecsxtal.com/store/pdf/ECS-3225MV.pdf
D6 = LDT-N2804RI: Display Modules - LED Character and Numeric Red 7-Segment 3 Character Common Cathode 2V 10mA 0.394" H x 0.887" W x 0.240" D (10.00mm x 22.53mm x 6.10mm) 12-DIP (0.300", 7.62mm), 11 Leads; Current: 10mA; Manufacturer: Lumex; Part type: SEVEN SEGMENT; Voltage: 2V; Datasheet: https://www.lumex.com/spec/LDT-N2804RI.pdf
J7 = HEADER_14: Connector Header Through Hole 14 position 0.100" (2.54mm); MFR PART NO.: 0022284141; Manufacturer: Molex; PACKAGE: TH; PART DESCRIPTION: CONN HEADER VERT 14POS 2.54MM; Part Type: Connector; Datasheet: https://www.molex.com/pdm_docs/sd/022284144_sd.pdf
R93-R100 = R: 53.6 Ohms ±1% 0.063W, 1/16W Chip Resistor 0402 (1005 Metric) Moisture Resistant Thick Film; MFR PART NO.: RC0603FR-0753R6L; Manufacturer: Yageo; Manufacturer Part Number: RC0402FR-0753R6L; PACKAGE: 0603; PART DESCRIPTION: RES 53.6 OHM 1% 1/10W 0603; Part Number: RC0402FR-0753R6L; Part type: Thick Film; Populate: DI; Power: 1/16W; Tolerance: 1%; Datasheet: https://www.yageo.com/upload/media/product/productsearch/datasheet/rchip/PYu-RC_Group_51_RoHS_L_12.pdf
R251-R254 = R: 1 kOhms ±1% 0.063W, 1/16W Chip Resistor 0402 (1005 Metric) Thick Film; Assy: DNL; Manufacturer: Yageo; Manufacturer Part Number: RC0402FR-71K2P / RC0402FR-0733R2P; Part Number: RC0402FR-071KP / RC0402FR-0733R2P / RC0402FR-0733R2P; Part type: Thick Film; Power: 1/16W; Tolerance: 1%; Datasheet: https://www.yageo.com/upload/media/product/products/datasheet/rchip/PYu-RC_51_RoHS_P_4.pdf
C46-C49 = CAP_NP: 0.22 µF ±10% 50V Ceramic Capacitor X5R 0402 (1005 Metric); Manufacturer: Murata; Manufacturer Part Number: GRM155R61H224KE01W; Part Number: GRM155R61H224KE01W; Part type: Ceramic; Tolerance: 10%; Voltage: 50V; Datasheet: https://search.murata.co.jp/Ceramy/image/img/A01X/G101/ENG/GRM155R61H224KE01-01A.pdf
J5 = HEADER_10: Connector Header Through Hole 10 position 0.100" (2.54mm); MFR PART NO.: 0022284101; Manufacturer: Molex; PACKAGE: TH; PART DESCRIPTION: CONN HEADER VERT 10POS 2.54MM; Part Type: Connector; Datasheet: https://www.molex.com/pdm_docs/sd/022284105_sd.pdf
J6 = HEADER_7X2: Connector Header Through Hole 14 position 0.100" (2.54mm); Manufacturer: Adam Tech; Part Type: Connector; Datasheet: https://app.adam-tech.com/products/download/data_sheet/202065/ph2-xx-ua-data-sheet.pdf
R85 R87 R89 R91 = R: 49.9 Ohms ±1% 0.063W, 1/16W Chip Resistor 0402 (1005 Metric) Moisture Resistant Thick Film; Manufacturer: Yageo; Manufacturer Part Number: RC0402FR-0749R9L; Part Number: RC0402FR-0749R9L; Part type: Thick Film; Power: 1/16W; Tolerance: 1%; Datasheet: https://www.yageo.com/upload/media/product/app/datasheet/rchip/pyu-rc_group_51_rohs_l.pdf
SW4 = SW_DIP-4: Dip Switch SPST 4 Position Surface Mount Slide (Standard) Actuator 100mA 20VDC / Dip Switch SPST 5 Position Surface Mount Slide (Standard) Actuator 100mA 20VDC; Manufacturer: CST; Datasheet: https://www.ctscorp.com/wp-content/uploads/219.pdf
SW6 = SW_DIP-8: Dip Switch SPST 8 Position Surface Mount Slide (Standard) Actuator 100mA 20VDC / Dip Switch SPST 5 Position Surface Mount Slide (Standard) Actuator 100mA 20VDC; MFR PART NO.: TDA08H0SB1; Manufacturer: CST; PACKAGE: SMD; PART DESCRIPTION: SWITCH SLIDE DIP SPST 25MA 24V; Datasheet: https://www.ctscorp.com/wp-content/uploads/219.pdf
U1 = LFMXO5D-100-BBG400: GHz BGA Socket - Direct mount, solderless; Manufacturer: Ironwood Electronics; PACKAGE: BBG400; PART DESCRIPTION: BGA Socket; gold plated wire elastomer; Datasheet: https://www.ironwoodelectronics.com/catalog/Content/Drawings/SG-BGA-6129Dwg.pdf

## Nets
GND: C1.2 C2.2 C3.2 C4.2 C5.2 C6.2 C7.2 C8.2 C9.2 C10.2 C11.2 C12.2 C13.2 C14.2 C15.2 C16.2 C17.1 C18.2 C19.1 C20.2 C25.2 C26.2 C27.2 C28.2 C29.2 C30.2 C31.2 C32.2 C33.2 C34.2 C35.2 C36.2 C37.2 C38.2 C39.2 C40.2 C41.2 C42.2 C43.2 C44.2 C45.2 C50.2 C51.2 C52.2 C53.2 C54.2 C55.2 C56.2 C133.2 D1.K(CATHODE) D2.1(GND) D4.2 J2.5(GND) J2.6(CASE1) J2.7(CASE2) J2.8(CASE3) J2.9(CASE4) J4.2 J4.10 J5.10 J6.2 J6.4 J6.8 J6.10 J6.14 J7.14 J22.2 J22.10 JP4.2 JP5.1 JP15.2 Q1.E R6.1 R43.2 R56.2 R88.2 R92.2 R255.2 R256.2 R257.2 R258.2 R558.2 R561.2 SW1.2 SW1.4 SW2.1 SW2.3 SW3.1 SW3.3 SW4.6(B3) SW4.7(B2) SW4.8(B1) SW5.1 SW5.3 SW6.9(B8) SW6.10(B7) SW6.11(B6) SW6.12(B5) SW6.13(B4) SW6.14(B3) SW6.15(B2) SW6.16(B1) TP1.1 TP8.1 TP9.1 TP10.1 TP76.1 U4.1(GND) U4.5(GND_1) U4.10(AGND) U4.11(GND_2) U4.13(TEST) U4.15(GND_3) U4.25(GND_4) U4.35(GND_5) U4.47(GND_6) U4.51(GND_7) U5.5(VSS) U7.4(GND) U12.4(GND) X1.2 X1.4 X2.2(GND) ; also on sheet 8 9 10 11 12 13 14 15 16 17 18 19 20 21 22 23 24 25 26 27 28
VBUS_5V_S: C13.1 D2.6(VBUS) FB3.1 R1.1 ; also on sheet 17
VBUS_S: FB3.2 J2.1(VCC)
VCC1V8FT_S: C3.1 C4.1 C5.1 C14.1 C15.1 FB4.2 U4.12(VCORE) U4.37(VCORE_1) U4.64(VCORE_2)
VCC_1V8: R68.1 R70.1 R75.1 R77.1 R78.1 R79.1 R80.1 R81.1 R82.1 R83.1 R84.1 R86.1 R90.1 ; also on sheet 8 9 11 15 16 18 20 26 27 28
VCC_3V3: C6.1 C7.1 C8.1 C9.1 C10.1 C16.1 C18.1 C20.1 C29.1 C133.1 FB1.2 FB2.2 J5.1 J6.1 J7.1 R2.2 R3.2 R4.2 R5.1 R7.1 R10.1 R11.1 R12.1 R34.1 R35.1 R36.1 R44.1 R45.1 R53.1 R54.1 R55.1 R57.1 R58.1 R59.1 R61.2 R62.1 R63.2 R66.2 R67.1 R71.1 R72.1 R73.1 R101.1 R102.1 R103.1 R104.1 R105.1 R106.1 R107.1 R108.1 R109.1 R110.1 R111.1 R112.1 R245.1 R246.1 R251.1 R252.1 R253.1 R254.1 R553.1 R554.1 R557.1 R559.1 R560.1 R562.1 R563.1 U4.20(VCCIO) U4.31(VCCIO_1) U4.42(VCCIO_2) U4.50(VREGIN) U4.56(VCCIO_3) U5.6(ORG) U5.8(VCC) U7.8(VCC) U12.8(VCC) X2.4(VDD) ; also on sheet 9 10 11 12 13 14 16 17 19 20 21 22 23 24 25 26 28
VCCIO0_3V3_XO5D: C30.1 C31.1 C32.1 U1.E14(VCCIO0) ; also on sheet 9
VCCIO1_3V3_XO5D: C25.1 C26.1 C27.1 C28.1 U1.C18(VCCIO1) U1.D17(VCCIO1) ; also on sheet 9
VCCIO2_3V3_XO5D: C51.1 C52.1 C53.1 U1.K18(VCCIO2) ; also on sheet 9
VCCIO5_1V8_XO5D: C41.1 C42.1 C43.1 C44.1 U1.R6(VCCIO5) U1.U3(VCCIO5) ; also on sheet 9
VCCIO6_3V3_XO5D: C54.1 C55.1 C56.1 U1.L4(VCCIO6) ; also on sheet 9
VCCIO7_3V3_XO5D: C35.1 C36.1 C37.1 C38.1 U1.F4(VCCIO7) U1.G5(VCCIO7) ; also on sheet 9
AWK1_X5_CS: J4.9 R35.2 U1.H18(PR38A)
AWK1_X5_MCLK: R36.2 R43.1 R50.2 U1.G19(PR29A/PCLKT1_1)
AWK1_X5_SI: J4.8 R53.2 U1.H17(PR38B)
AWK1_X5_SO: J4.5 U1.H14(PR33A)
D+S: D2.2(NC2) D2.5(D+) J2.3(D+) U4.8(DP)
D-S: D2.3(NC3) D2.4(D-) J2.2(D-) U4.7(DM)
EEPROM_ADR_A0_R: R253.2 R257.1 U12.1(A0)
EEPROM_ADR_A1_R: R252.2 R256.1 U12.2(A1)
EEPROM_ADR_A2_R: R251.2 R255.1 U12.3(A2)
EEPROM_WP: R254.2 R258.1 U12.7(WP)
FT_EECLK_S: R11.2 U4.62(EECLK) U5.2(CLK)
FT_EECS_S: R10.2 U4.63(EECS) U5.1(CS)
FT_EEDATA_S: R13.1 U4.61(EEDATA) U5.3(DI)
FT_OSCI_S: C17.2 U4.2(OSCI) X1.1
FT_OSCO_S: C19.2 U4.3(OSCO) X1.3
FT_REF_S: R6.2 U4.6(REF)
FT_RSTn: JP4.1 R4.1 U4.14(~{RESET#})
FT_VPHY_S: C1.1 C2.1 FB1.1 U4.4(VPHY)
FT_VPLL_S: C11.1 C12.1 FB2.1 U4.9(VPLL)
NX_PROGRAMN: U1.A15(PT156B) ; also on sheet 12
NX_X5_I2C_FLT0_SCL_I: R45.2 U1.A19(PR11B/SCL) ; also on sheet 11
NX_X5_I2C_FLT0_SDA_I: R44.2 U1.A18(PR11A/SDA) ; also on sheet 11
NX_X5_I3C_SCL_0: U1.N4(PL65B) ; also on sheet 13
NX_X5_I3C_SCL_1: U1.L3(PL53B) ; also on sheet 13
NX_X5_I3C_SCL_2: U1.L17(PR64A) ; also on sheet 13
NX_X5_I3C_SCL_3: U1.J4(PL38A) ; also on sheet 13
NX_X5_I3C_SDA_0: U1.N5(PL67A) ; also on sheet 13
NX_X5_I3C_SDA_1: U1.L6(PL55A) ; also on sheet 13
NX_X5_I3C_SDA_2: U1.L16(PR64B) ; also on sheet 13
NX_X5_I3C_SDA_3: U1.J5(PL38B) ; also on sheet 13
NX_X5_INT_SIDEBAND: R60.1 ; also on sheet 12
NX_X5_RND_SIDEBAND: U1.D15(PT154B) ; also on sheet 12
NX_X5_SIDEBAND_D0: U1.B15(PT156A) ; also on sheet 12
NX_X5_SIDEBAND_D1: U1.E13(PT150A) ; also on sheet 12
NX_X5_SIDEBAND_D2: U1.E12(PT150B) ; also on sheet 12
NX_X5_SIDEBAND_D3: U1.D14(PT152A) ; also on sheet 12
NX_X5_SIDEBAND_D4: U1.C15(PT154A) ; also on sheet 12
QMON0_CSN0: R14.1 U1.F18(PR22A)
QMON0_CSN1: R15.1 U1.E18(PR22B)
QMON0_DQ2: R23.1 U1.F19(PR24A)
QMON0_DQ3: R27.1 U1.G16(PR26A)
QMON0_MISO_DQ1: R22.1 U1.G18(PR28B)
QMON0_MOSI_DQ0: R21.1 U1.E19(PR24B)
QMON0_SCLK: R20.1 U1.G17(PR28A/PCLKT1_2)
QSPI_MON0_CS0_I: R14.2 ; also on sheet 22
QSPI_MON0_CS0_O: R593.2 ; also on sheet 22
QSPI_MON0_CS1_I: R15.2 ; also on sheet 22
QSPI_MON0_CS1_O: R594.2 ; also on sheet 22
QSPI_MON0_FLASH_CLK: R20.2 ; also on sheet 22
QSPI_MON0_FLASH_DQ0: R21.2 ; also on sheet 22
QSPI_MON0_FLASH_DQ1: R22.2 ; also on sheet 22
QSPI_MON0_FLASH_DQ2: R23.2 ; also on sheet 22
QSPI_MON0_FLASH_DQ3: R27.2 ; also on sheet 22
QSPI_MON0_QS_DISABLE: U1.D16(PR10A) ; also on sheet 22
QSPI_MON0_QS_SEL: U1.C17(PR8A) ; also on sheet 22
QSPI_MON1_CLK: R117.1 U1.K2(PL44A/PCLKT6_1)
QSPI_MON1_CS0: R113.1 U1.K4(PL46A/PCLKT6_2)
QSPI_MON1_CS0_I: R113.2 ; also on sheet 23
QSPI_MON1_CS0_O: R595.2 ; also on sheet 23
QSPI_MON1_CS1: R114.1 U1.K5(PL46B)
QSPI_MON1_CS1_I: R114.2 ; also on sheet 23
QSPI_MON1_CS1_O: R596.2 ; also on sheet 23
QSPI_MON1_DQ0: R118.1 U1.K3(PL44B)
QSPI_MON1_DQ1: R119.1 U1.K6(PL47A)
QSPI_MON1_DQ2: R120.1 U1.K7(PL47B)
QSPI_MON1_DQ3: R121.1 U1.J9(PL49A)
QSPI_MON1_FLASH_CLK: R117.2 ; also on sheet 23
QSPI_MON1_FLASH_DQ0: R118.2 ; also on sheet 23
QSPI_MON1_FLASH_DQ1: R119.2 ; also on sheet 23
QSPI_MON1_FLASH_DQ2: R120.2 ; also on sheet 23
QSPI_MON1_FLASH_DQ3: R121.2 ; also on sheet 23
QSPI_MON2_QS_DISABLE: U1.N3(PL65A) ; also on sheet 23
QSPI_MON2_QS_SEL: U1.J8(PL42B) ; also on sheet 23
TCK: JP1.2 U4.16(ADBUS0) ; also on sheet 24
TDI: JP2.2 U4.17(ADBUS1) ; also on sheet 24
TDO: U4.18(ADBUS2) ; also on sheet 24
TMS: U4.19(ADBUS3) ; also on sheet 24
X3_UART_RXD: JP2.1 R3.1 ; also on sheet 19
X3_UART_TXD: JP1.1 R2.1 ; also on sheet 19
X3_X5_I2C_FLT1_SCL_I: R554.2 U1.M2(PL56B) ; also on sheet 17
X3_X5_I2C_FLT1_SDA_I: R553.2 U1.M1(PL56A) ; also on sheet 17
X3_X5_MPESTI-GPIO_0: U1.F7(PL15B) ; also on sheet 21
X3_X5_MPESTI-GPIO_1: U1.F2(PL17B) ; also on sheet 21
X3_X5_MPESTI-T_0: U1.F3(PL17A) ; also on sheet 21
X3_X5_MPESTI-T_1: U1.G3(PL19A) ; also on sheet 21
X3_X5_MPESTI-T_2: U1.G2(PL19B) ; also on sheet 21
X5_CSN: J6.13 R562.2 U1.H8(PL26B)
X5_DIP_SW1: R84.2 SW6.1(A1) U1.P2(PB2A/LLC_GPLL0T_IN/CDR_RXP0/VREF5_1/ADC_CP0/COMP1P)
X5_DIP_SW2: R83.2 SW6.2(A2) U1.R2(PB2B/LLC_GPLL0C_IN/CDR_RXN0/ADC_CN0/COMP1N)
X5_DIP_SW3: R82.2 SW6.3(A3) U1.U2(PB26A)
X5_DIP_SW4: R81.2 SW6.4(A4) U1.P5(PB4B/PCLKC5_0/CDR_RXN1/ADC_CN1/COMP2N)
X5_DIP_SW5: R80.2 SW6.5(A5) U1.P1(PB6A)
X5_DIP_SW6: R79.2 SW6.6(A6) U1.R1(PB6B)
X5_DIP_SW7: R78.2 SW6.7(A7) U1.R4(PB8A/ADC_CP3)
X5_DIP_SW8: R77.2 SW6.8(A8) U1.P4(PB8B/ADC_CN3)
X5_DONE: R63.1 R65.2 TP2.1 U1.H11(PT136B/DONE)
X5_EEPROM_1_ADR_A0: U1.F15(PR15A) U7.1(A0)
X5_EEPROM_1_ADR_A1: U1.F16(PR15B) U7.2(A1)
X5_EEPROM_1_ADR_A2: U1.F17(PR17A) U7.3(A2)
X5_EEPROM_1_WP: U1.E17(PR17B) U7.7(WP)
X5_FLASHA_RSTN: U1.L15(PR65A) ; also on sheet 23
X5_FLASHB_RSTN: U1.L14(PR65B) ; also on sheet 23
X5_FLASHC_RSTN: U1.M20(PR67A) ; also on sheet 22
X5_FLASHD_RSTN: U1.M19(PR67B) ; also on sheet 22
X05_HPM_RXCLK_N: U1.P3(PB10B/PCLKC5_1/ADC_CN2/COMP3N) ; also on sheet 26
X05_HPM_RXCLK_P: U1.R3(PB10A/PCLKT5_1/ADC_CP2/COMP3P) ; also on sheet 26
X05_HPM_RXD_N: U1.P7(PB12B) ; also on sheet 26
X05_HPM_RXD_P: U1.P6(PB12A) ; also on sheet 26
X05_HPM_TXCLK_N: U1.U1(PB30B) ; also on sheet 26
X05_HPM_TXCLK_P: U1.T1(PB30A) ; also on sheet 26
X05_HPM_TXD_N: U1.T4(PB32B) ; also on sheet 26
X05_HPM_TXD_P: U1.U4(PB32A) ; also on sheet 26
X5_I2C_FLT0_SCL_O: J4.1 R54.2 U1.H16(PR35B) U7.6(SCL)
X5_I2C_FLT0_SDA_O: J4.3 R55.2 U1.H15(PR35A) U7.5(SDA)
X5_I2C_FLT1_SCL_O: J22.1 R245.2 U1.N1(PL64A) U12.6(SCL)
X5_I2C_FLT1_SDA_O: J22.3 R246.2 U1.N2(PL64B) U12.5(SDA)
X5_IF_TCK: J6.3 R558.1 U1.H3(PL31A/PCLKT7_0)
X5_IF_TDI: J6.5 R559.2 U1.H4(PL29B)
X5_IF_TDO: J6.6 R557.2 U1.H2(PL31B)
X5_IF_TMS: J6.7 R560.2 U1.H1(PL33A)
X5_INITN: D5.K(CATHODE) R66.1 TP4.1 U1.H10(PT134A/INITN)
X5_K_DIG1: D6.12(K_DIG1) U1.J11(PR49A)
X5_K_DIG2: D6.9(K_DIG2) U1.J12(PR49B)
X5_K_DIG3: D6.8(K_DIG3) U1.K10(PR51A)
X5_MCLK: J6.9 R561.1 U1.H6(PL28A/PCLKT7_2)
X5_MISO: J6.12 R563.2 U1.H7(PL28B)
X5_MODE0: R71.2 SW4.1(A1) U1.J1(PL33B)
X5_MODE1: R72.2 SW4.2(A2) U1.J2(PL35A)
X5_MODE2: R73.2 SW4.3(A3) U1.J3(PL35B)
X5_MOSI: J6.11 U1.H5(PL29A/PCLKT7_1)
X5_NX_I2C1_SCL: U1.M18(PR62B) ; also on sheet 12
X5_NX_I2C1_SDA: U1.L18(PR62A) ; also on sheet 12
X5_NX_SGPIOA_0: J5.2 U1.C2(PL3A/ULC_GPLL0T_IN) ; also on sheet 14
X5_NX_SGPIOA_1: J5.3 U1.D2(PL3B) ; also on sheet 14
X5_NX_SGPIOA_2: J5.4 U1.E1(PL4A) ; also on sheet 14
X5_NX_SGPIOA_3: J5.5 U1.D1(PL4B) ; also on sheet 14
X5_NX_SGPIOB_0: J5.6 U1.E3(PL6A) ; also on sheet 14
X5_NX_SGPIOB_1: J5.7 U1.E4(PL6B) ; also on sheet 14
X5_NX_SGPIOB_2: J5.8 U1.E5(PL8A) ; also on sheet 14
X5_NX_SGPIOB_3: J5.9 U1.E2(PL8B) ; also on sheet 14
X5_OSC_EN: JP5.2 R34.2 U1.E20(PR31B) X2.1(~{SHDN})
X5_OSC_IN: R37.2 U1.F20(PR31A/PCLKT1_0)
X5_PB1: C34.1 R69.2 TP5.1 U1.T2(PB26B)
X5_PB2: C39.1 R74.2 TP6.1 U1.T5(PB28A)
X5_PB3: C40.1 R76.2 TP7.1 U1.U5(PB28B)
X5_PROGRAMN: C33.1 JP15.1 R64.2 U1.G10(PT134B/PROGRAMN)
X5_SEG_A_B: R94.1 U1.K19(PR58A)
X5_SEG_B_B: R95.1 U1.K15(PR56B)
X5_SEG_C_B: R96.1 U1.K16(PR56A)
X5_SEG_D_B: R97.1 U1.K11(PR55B)
X5_SEG_DP_B: R93.1 U1.J10(PR51B)
X5_SEG_E_B: R98.1 U1.K12(PR55A)
X5_SEG_F_B: R99.1 U1.K13(PR53B)
X5_SEG_G_B: R100.1 U1.K14(PR53A)
X5_STRAP_PIN_0: JP14.2 U1.G12(PT144A)
X5_STRAP_PIN_1: JP14.1 U1.H12(PT144B)
X5_TCK: U1.B19(PR13A/TCK/SCLK/PMU_EXT_CLK) ; also on sheet 24
X5_TDI: U1.C16(PR8B/TDI/SSI) ; also on sheet 24
X5_TDO: U1.E16(PR10B/TDO/SSO) ; also on sheet 24
X5_TMS: U1.B16(PR6B/TMS/SCSN) ; also on sheet 24
X5_UART_RXD: R7.2 R9.2 U1.J7(PL40A)
X5_UART_TXD: R5.2 R8.2 U1.J6(PL40B)
X5_X3_CFG_SCL: R58.2 U1.G13(PT148A) ; also on sheet 17
X5_X3_CFG_SDA: R59.2 U1.G14(PT148B) ; also on sheet 17
X5_X3_LTPI_RXCLK_N: R87.2 U1.Y3(PB40B/PCLKC5_2) ; also on sheet 17
X5_X3_LTPI_RXCLK_P: R85.1 U1.Y2(PB40A/PCLKT5_2) ; also on sheet 17
X5_X3_LTPI_RXD_N: R91.2 U1.W1(PB42B) ; also on sheet 17
X5_X3_LTPI_RXD_P: R89.1 U1.V1(PB42A) ; also on sheet 17
X5_X3_LTPI_TXCLK_N: C47.2 ; also on sheet 19
X5_X3_LTPI_TXCLK_N_DC: C47.1 U1.V5(PB36B)
X5_X3_LTPI_TXCLK_P: C46.2 ; also on sheet 19
X5_X3_LTPI_TXCLK_P_DC: C46.1 U1.V4(PB36A)
X5_X3_LTPI_TXD_N: C49.2 ; also on sheet 19
X5_X3_LTPI_TXD_N_DC: C49.1 U1.W3(PB38B)
X5_X3_LTPI_TXD_P: C48.2 ; also on sheet 19
X5_X3_LTPI_TXD_P_DC: C48.1 U1.W2(PB38A)
X5_X3_MPESTI-I_0: U1.F5(PL13A) ; also on sheet 21
X5_X3_MPESTI-I_1: U1.F6(PL13B) ; also on sheet 21
X5_X3_MPESTI-I_2: U1.E8(PL15A) ; also on sheet 21
X_CC_SMBUS_ALERTN0: J7.4 R103.2 U1.J20(PR42A/PCLKT2_0) ; also on sheet 14
X_CC_SMBUS_ALERTN1: J7.7 R106.2 U1.J17(PR44B) ; also on sheet 14
X_CC_SMBUS_ALERTN2: J7.10 R109.2 U1.J14(PR47A) ; also on sheet 14
X_CC_SMBUS_ALERTN3: J7.13 R112.2 U1.L19(PR60B) ; also on sheet 14
X_CC_SMBUS_SCL0: J7.2 R101.2 U1.H20(PR40A) ; also on sheet 14
X_CC_SMBUS_SCL1: J7.5 R104.2 U1.J19(PR42B) ; also on sheet 14
X_CC_SMBUS_SCL2: J7.8 R107.2 U1.J16(PR46A/PCLKT2_2) ; also on sheet 14
X_CC_SMBUS_SCL3: J7.11 R110.2 U1.J13(PR47B) ; also on sheet 14
X_CC_SMBUS_SDA0: J7.3 R102.2 U1.H19(PR40B) ; also on sheet 14
X_CC_SMBUS_SDA1: J7.6 R105.2 U1.J18(PR44A/PCLKT2_1) ; also on sheet 14
X_CC_SMBUS_SDA2: J7.9 R108.2 U1.J15(PR46B) ; also on sheet 14
X_CC_SMBUS_SDA3: J7.12 R111.2 U1.L20(PR60A) ; also on sheet 14
X_JTAGENB: JP12.1 R56.1 U1.A14(JTAG_EN)
N16761500: JP12.2 R57.2
N16829737: D3.A(ANODE) R61.1
N16829756: D3.K(CATHODE) Q1.C
N16829794: Q1.B R65.1
N16830290: D5.A(ANODE) R67.2
N16830428: D4.1 R62.2 R64.1 SW1.1 SW1.3
N16833512: R37.1 X2.3(OUT)
N16852647: D6.3(DP) R93.2
N16852679: D6.11(A) R94.2
N16852705: D6.7(B) R95.2
N16852729: D6.4(C) R96.2
N16852737: D6.2(D) R97.2
N16852749: D6.1(E) R98.2
N16852758: D6.10(F) R99.2
N16852770: D6.5(G) R100.2
N16855625: R68.2 R69.1 SW2.2 SW2.4
N16855711: R70.2 R74.1 SW3.2 SW3.4
N16855792: R75.2 R76.1 SW5.2 SW5.4
N16937191: R60.2 U1.E15(PT152B)
N17003487: R12.2 R13.2 U5.4(DO)
N17003546: R9.1 U4.39(BDBUS1)
N17003556: R8.1 U4.38(BDBUS0)
N17656631: D1.A(ANODE) R1.2
N18008247: R595.1 U1.L1(PL51B)
N18008254: R596.1 U1.L2(PL53A)
N18863773: FB4.1 U4.49(VREGOUT)
N19780962: C50.1 R89.2 R90.2 R91.1 R92.1
N19784513: C45.1 R85.2 R86.2 R87.1 R88.1
N20085291: R593.1 U1.C20(PR20A)
N20085298: R594.1 U1.D20(PR20B)
N20096071: J4.7 R50.1

Not connected (* = marked no-connect by the designer): J2 4(NC)*; J4 4* 6*; J22 4* 5 6* 7 8 9; SW4 4(A4)* 5(B4)*; U1 A16(PR4B/URC_GPLL0C_IN) A17(PR4A/URC_GPLL0T_IN) B17(PR6A) B18(PR3B) B20(PR13B/PMU_WAKEUPN) C19(PR19A) D19(PR19B) E6(PL10A)* E7(PL10B)* F1(PL24B)* F8(PL22B)* F12(PT146B)* F13(PT146A)* G1(PL24A)* G6(PL20A)* G7(PL20B)* G8(PL22A)* G9(PL26A)* G11(PT142B/MCSNO/MSDO)* G15(PR26B) G20(PR29B) H9(PL49B)* H13(PR33B) K1(PL51A)* K8(PL42A/PCLKT6_0) K20(PR58B)* L7(PL55B)* M3(PL58A)* M4(PL58B)* M5(PL60A)* M6(PL60B) M7(PL62A) M8(PL62B) N6(PL67B)* R5(PB4A/PCLKT5_0/CDR_RXP1/ADC_CP1/COMP2P)* V2(PB34A)* V3(PB34B)* V6(PB48A)* W4(PB44A)* W5(PB46A/PCLKT5_3)* W6(PB48B/VREF5_2)* Y4(PB44B)* Y5(PB46B/PCLKC5_3)*; U4 21(ADBUS4) 22(ADBUS5) 23(ADBUS6) 24(ADBUS7) 26(ACBUS0) 27(ACBUS1) 28(ACBUS2) 29(ACBUS3) 30(ACBUS4) 32(ACBUS5) 33(ACBUS6) 34(ACBUS7) 36(~{SUSPEND#}) 40(BDBUS2) 41(BDBUS3) 43(BDBUS4) 44(BDBUS5) 45(BDBUS6) 46(BDBUS7) 48(BCBUS0) 52(BCBUS1) 53(BCBUS2) 54(BCBUS3) 55(BCBUS4) 57(BCBUS5) 58(BCBUS6) 59(BCBUS7) 60(~{PWREN#}); U5 7(NC)*

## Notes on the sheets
sheet 1
- LFMXO5D PFR Board
- Rev - A.1
- 01 - Title page
  02 - Block diagram
  03 - JTAG FTDI
  04 - LFMXO5D Bank1
  05 - LFMXO5D Bank0
  06 - LFMXO5D Bank5,7
  07 - LFMXO5D Bank2,6
  08 - LFMXO5D Bank3,4,ADC
  09 - LFMXO5D Power
  10 - Demo FTDI
  11 - CertusPro-NX Bank1,5 (BMC)
  12 - CertusPro-NX Bank0 (BMC)
  13 - CertusPro-NX Bank7 (BMC)
  14 - CertusPro-NX Bank2,6 (PCH)
  15 - CertusPro-NX Bank3,4,A (PCH)
  16 - CertusPro-NX Power
- 17 - LCMXO3D BANK0
  18 - LCMXO3D BANK1
  19 - LCMXO3D BANK2,3,4,5
  20 - LCMXO3D Power
  21 - MPESTI
  22 - BMC Flash
  23 - PCH Flash
  24 - JTAG Chain
  25 - LEDs
  26 - DC-SCM Connectors
  27 - I3C PU
  28 - Power Regulators
sheet 3
- JTAG FTDI
- U1_RST
sheet 4
- Place these resistors as close to
  U13 and U15 as possible to reduce stub
- BANK 1
  3.3V
- 50ohm trace
- OSCILLATOR 25MHZ
- 2.5 x 2.0 mm 4-SMD
- PLACE X2 CLOSE TO U1
- DNP
- EEPROM
- AARDVARK HEADER
sheet 5
- STRAP PIN HEADER
- BANK 0
  3.3V
- PROGRAMN
- DONE LED
- INITN LED
sheet 6
- SGPIO HEADER
- PB SWITCHES
- U1
  Pin
- Signal
- T2
- X5_PB1
- T5
- X5_PB2
- U5
- X5_PB3
- BANK 7
- 3.3V
- DIP Switch Signal Map
- U1
  Pin
- Signal
- SWITCH
- DIP SWITCH
- P2
- X5_DIP_SW1
- 1
- R2
- X5_DIP_SW2
- 2
- U2
- X5_DIP_SW3
- 3
- BANK 5
  1.8V
- P5
- X5_DIP_SW4
- 4
- P1
- X5_DIP_SW5
- 5
- R1
- X5_DIP_SW6
- 6
- R4
- X5_DIP_SW7
- 7
- P4
- X5_DIP_SW8
- 8
sheet 7
- SMBUS HEADER
- WR GPIO BANK
- BANK 2
- 3 DIGIT
  7-SEGMENT DISPLAY
- 3.3V
- Place these resistors as close to
  U21, U23 as possible to reduce stub
- EEPROM
- DNP
- BANK 6
  3.3V
- AARDVARK HEADER
